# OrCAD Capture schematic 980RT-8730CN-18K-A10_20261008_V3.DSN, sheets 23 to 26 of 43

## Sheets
23 P0071_S7_DUT1: size Custom
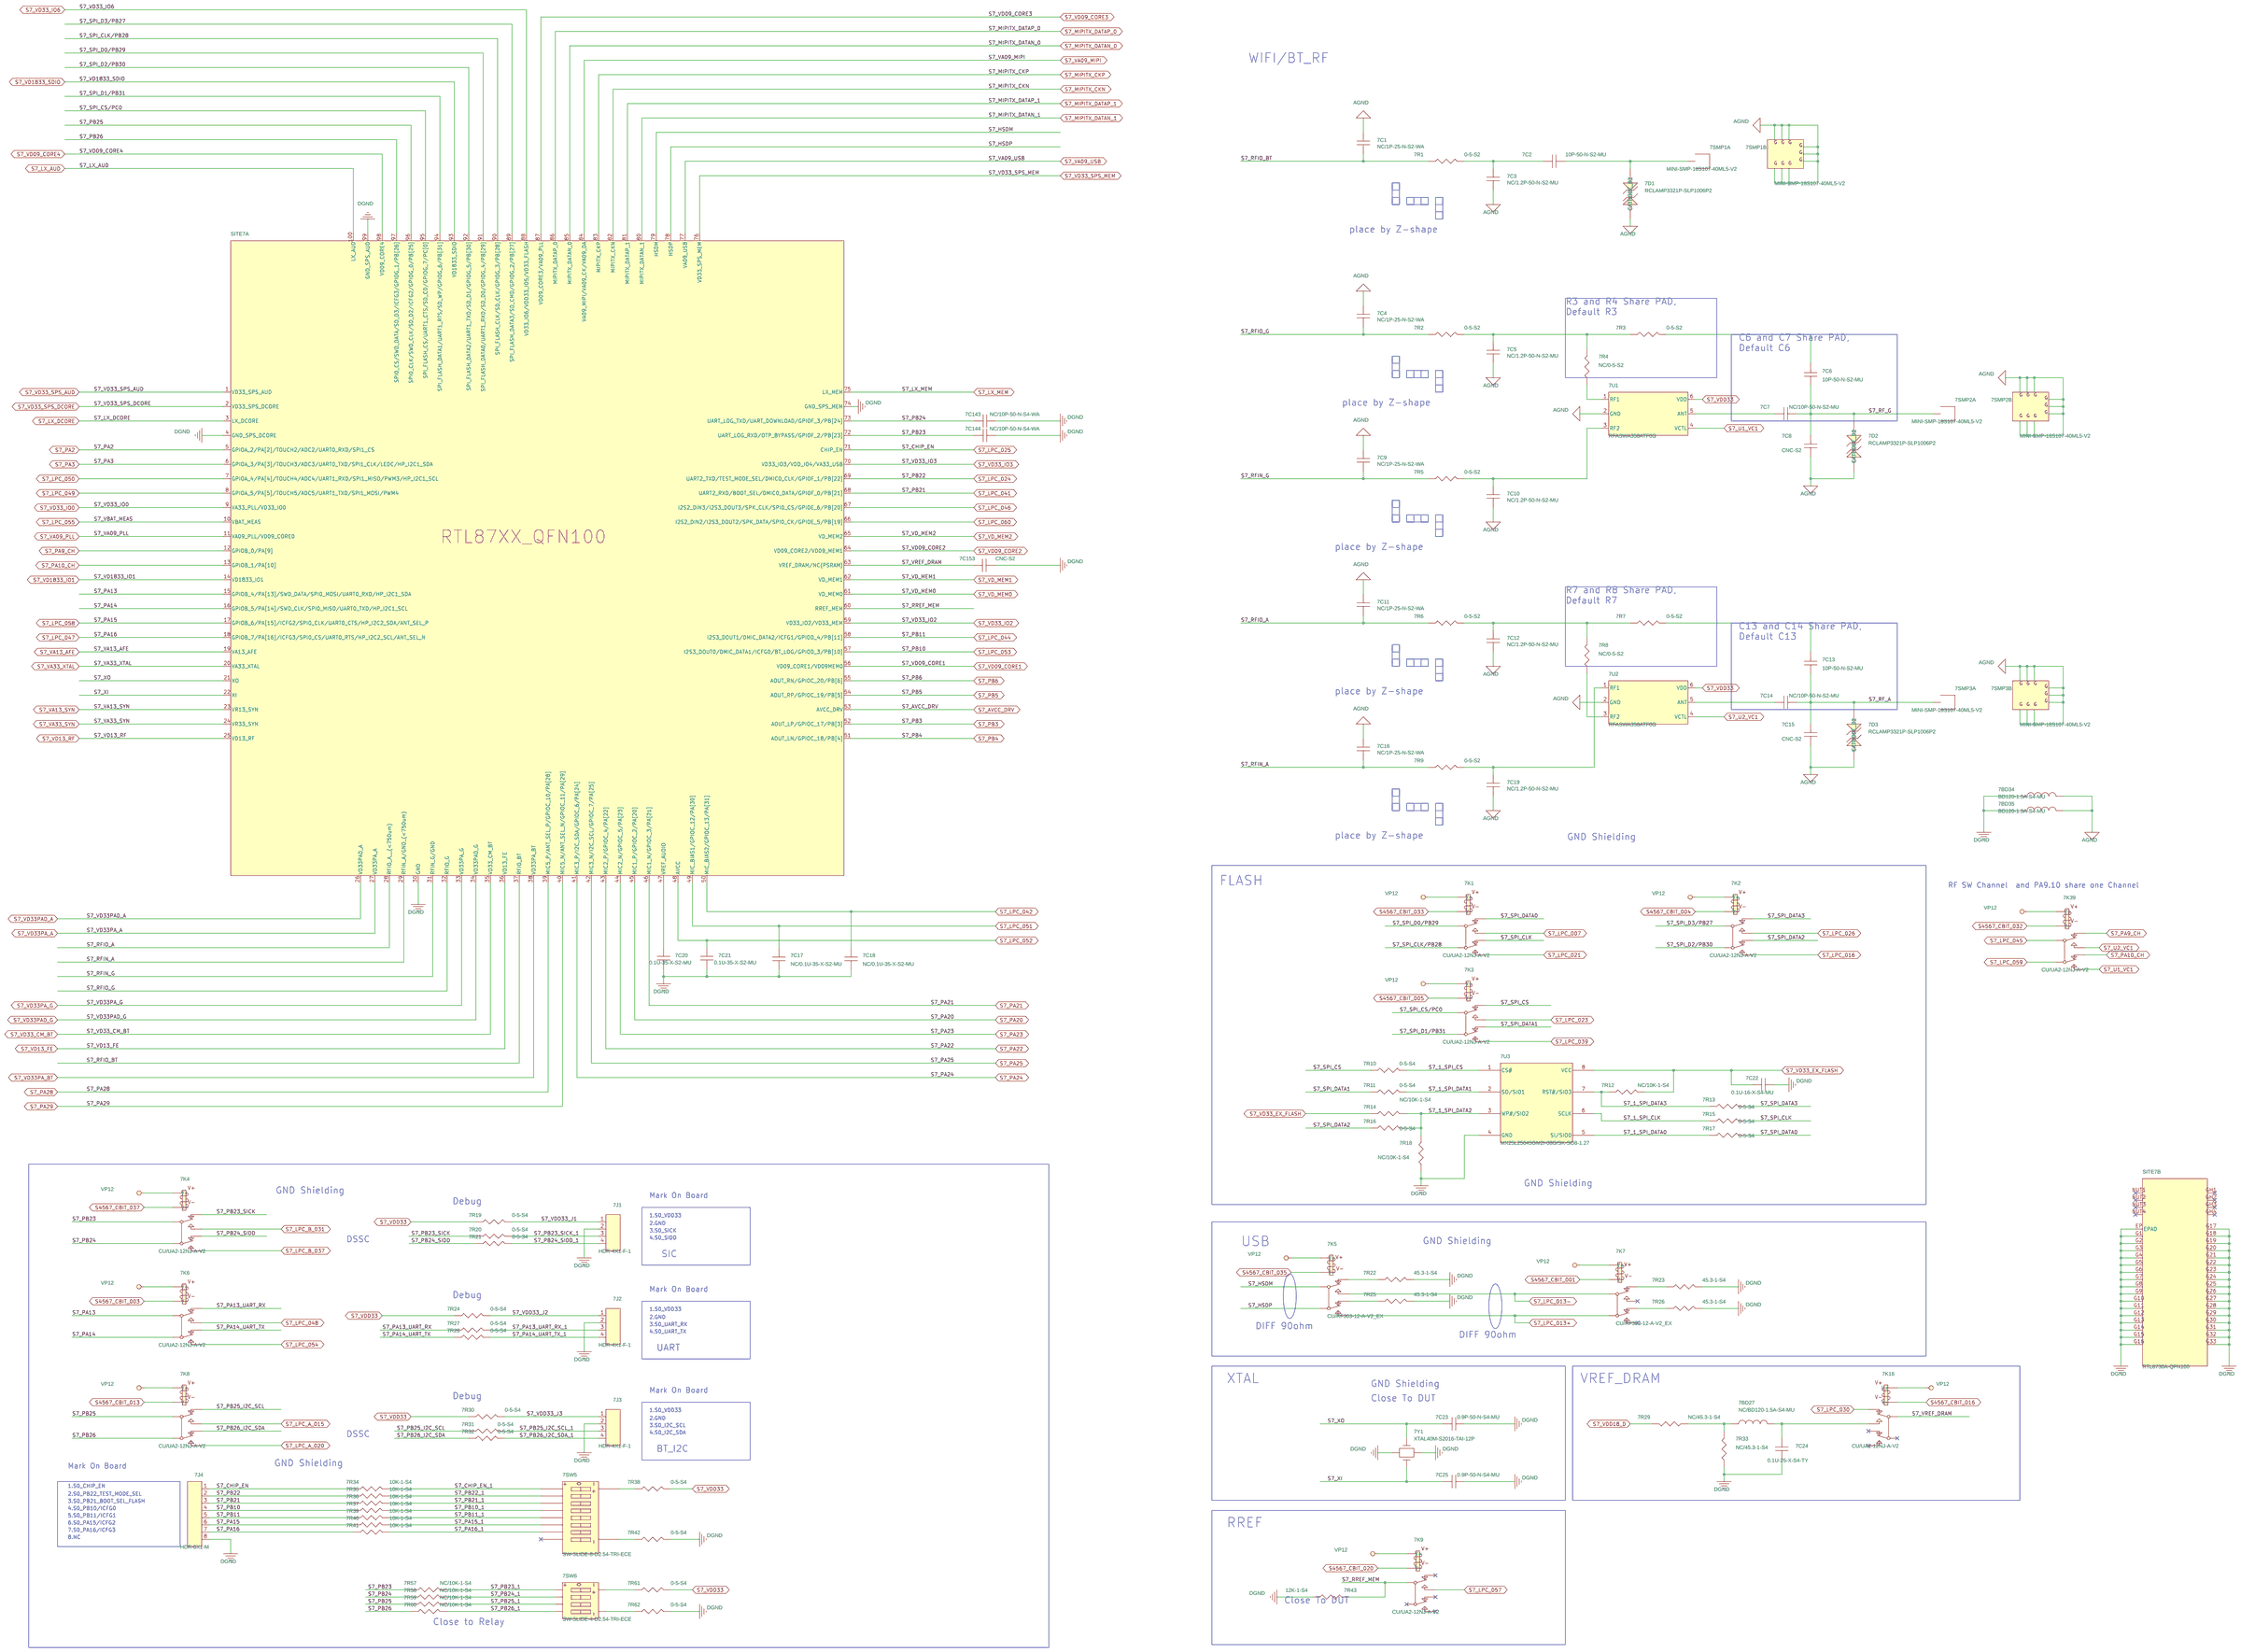
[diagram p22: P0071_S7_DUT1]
24 P0072_S7_Function-test: size A3
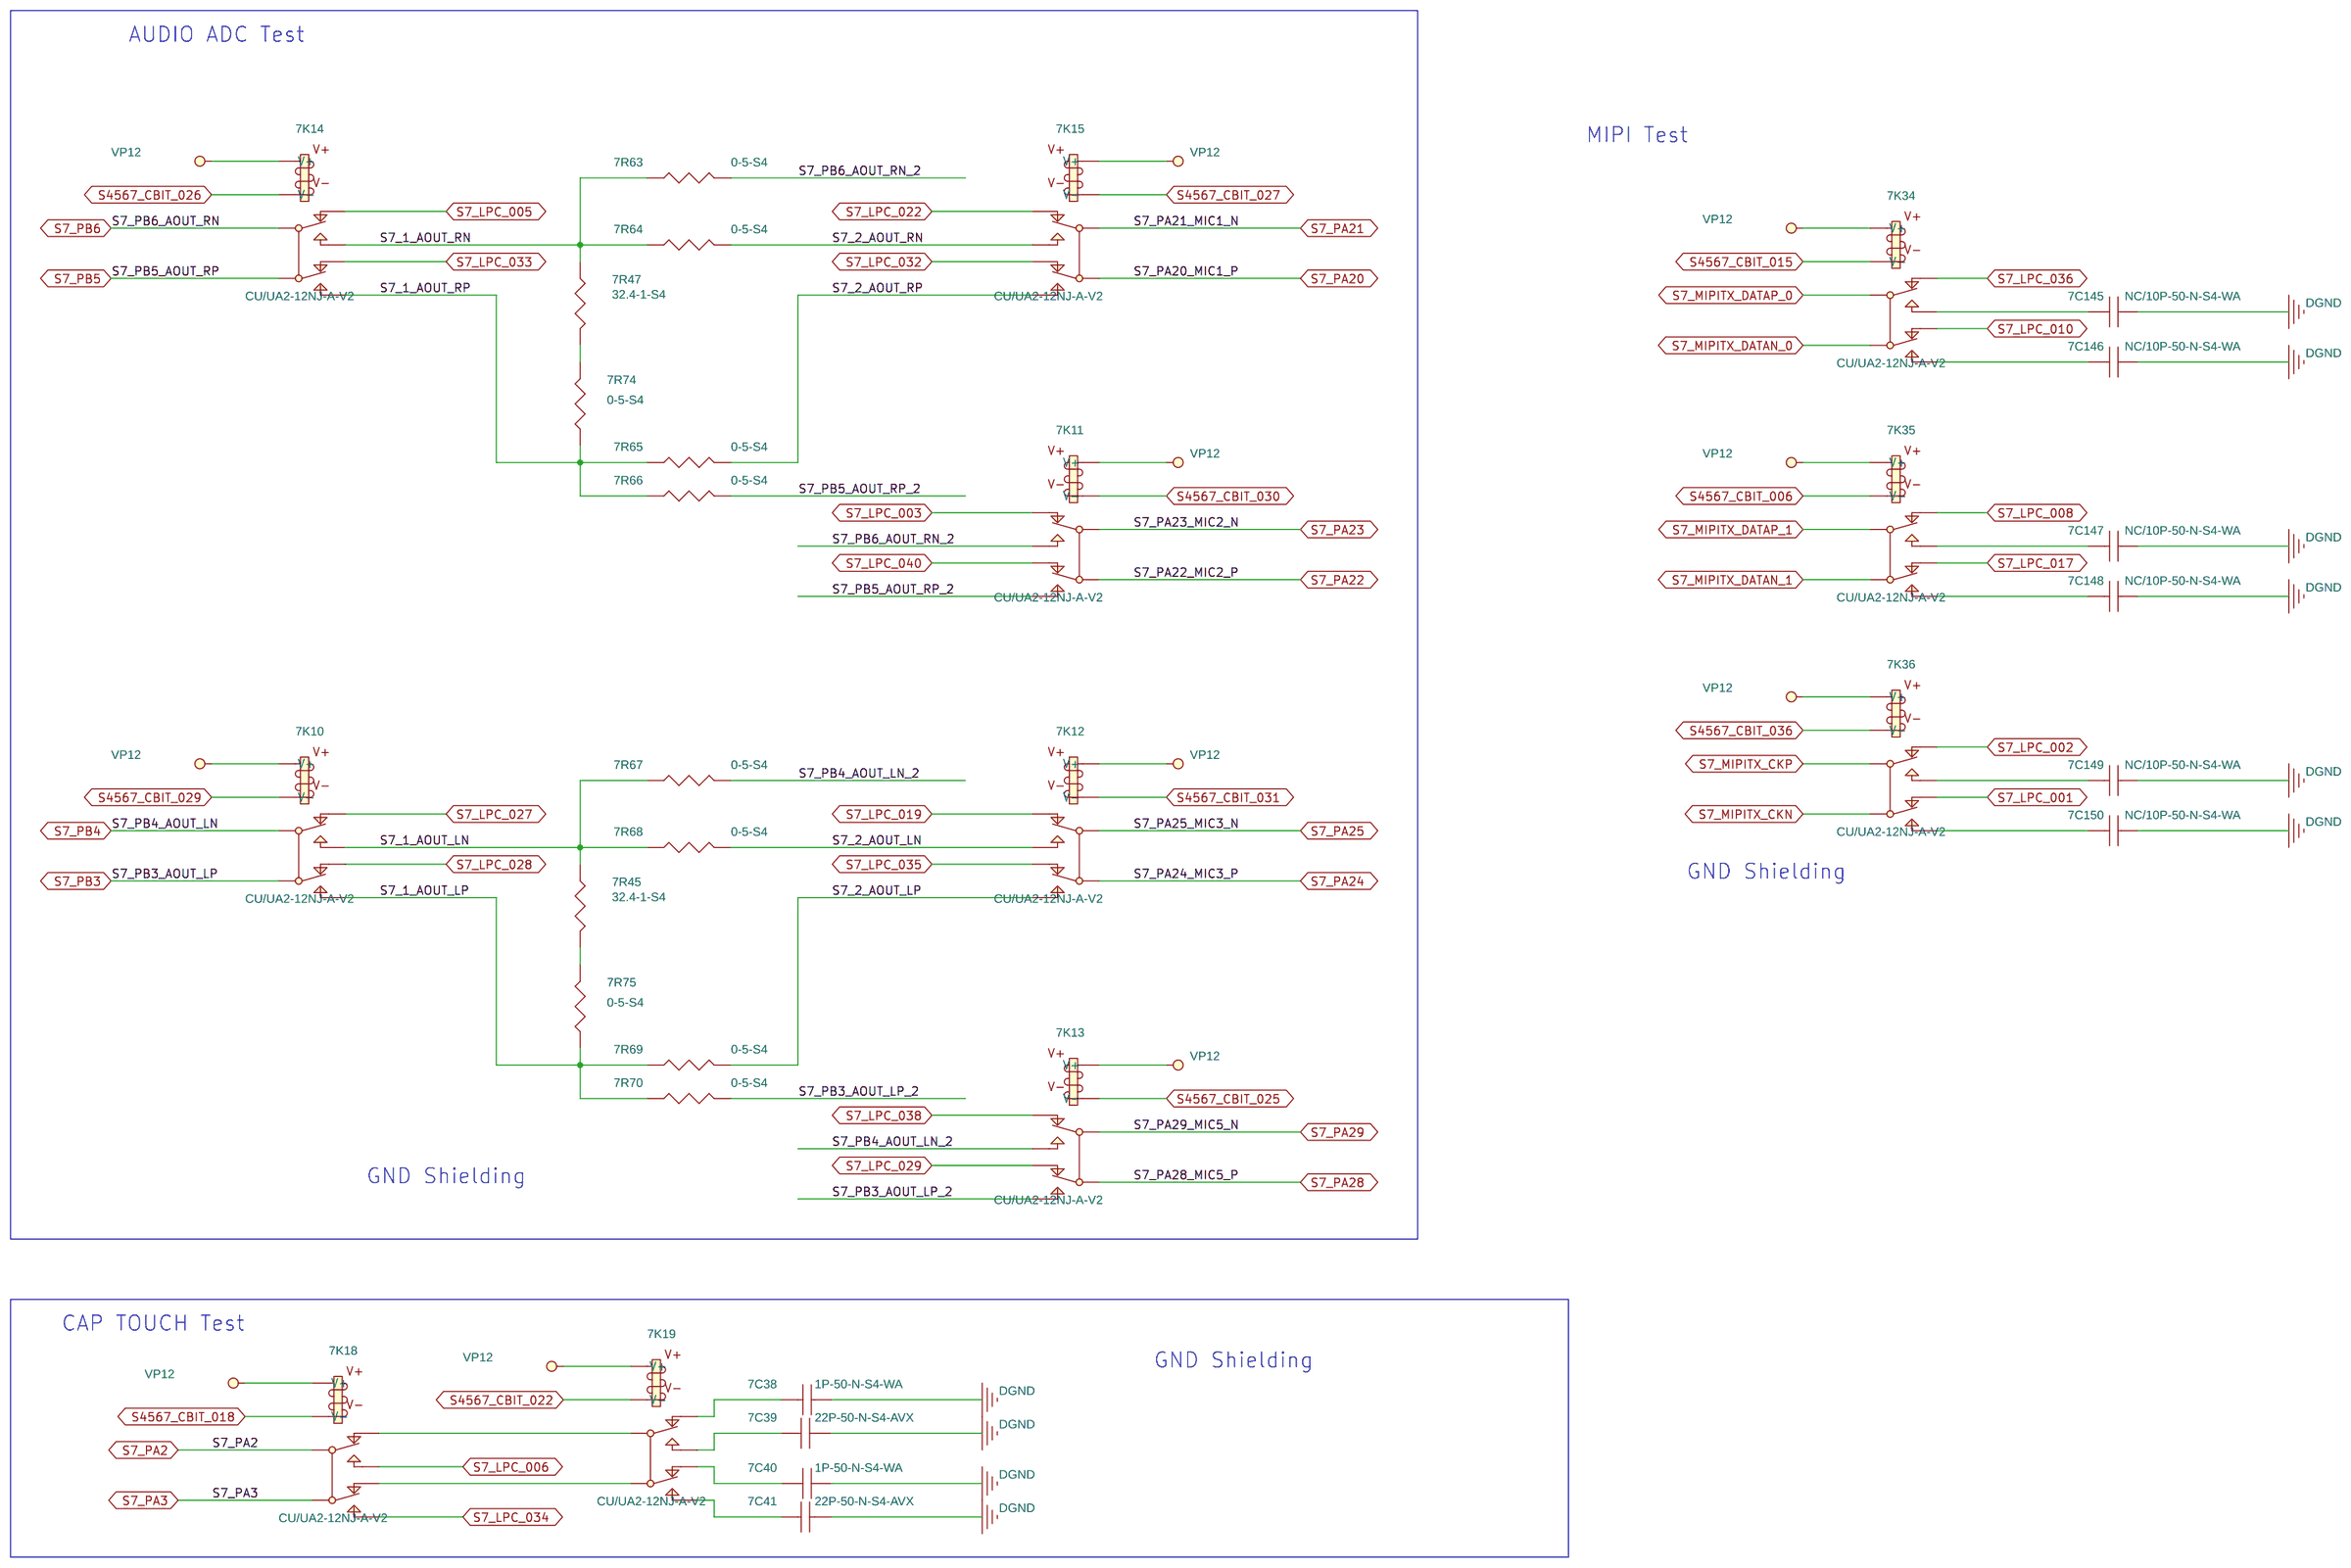
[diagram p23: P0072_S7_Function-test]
25 P0073_S7_Power: size A1
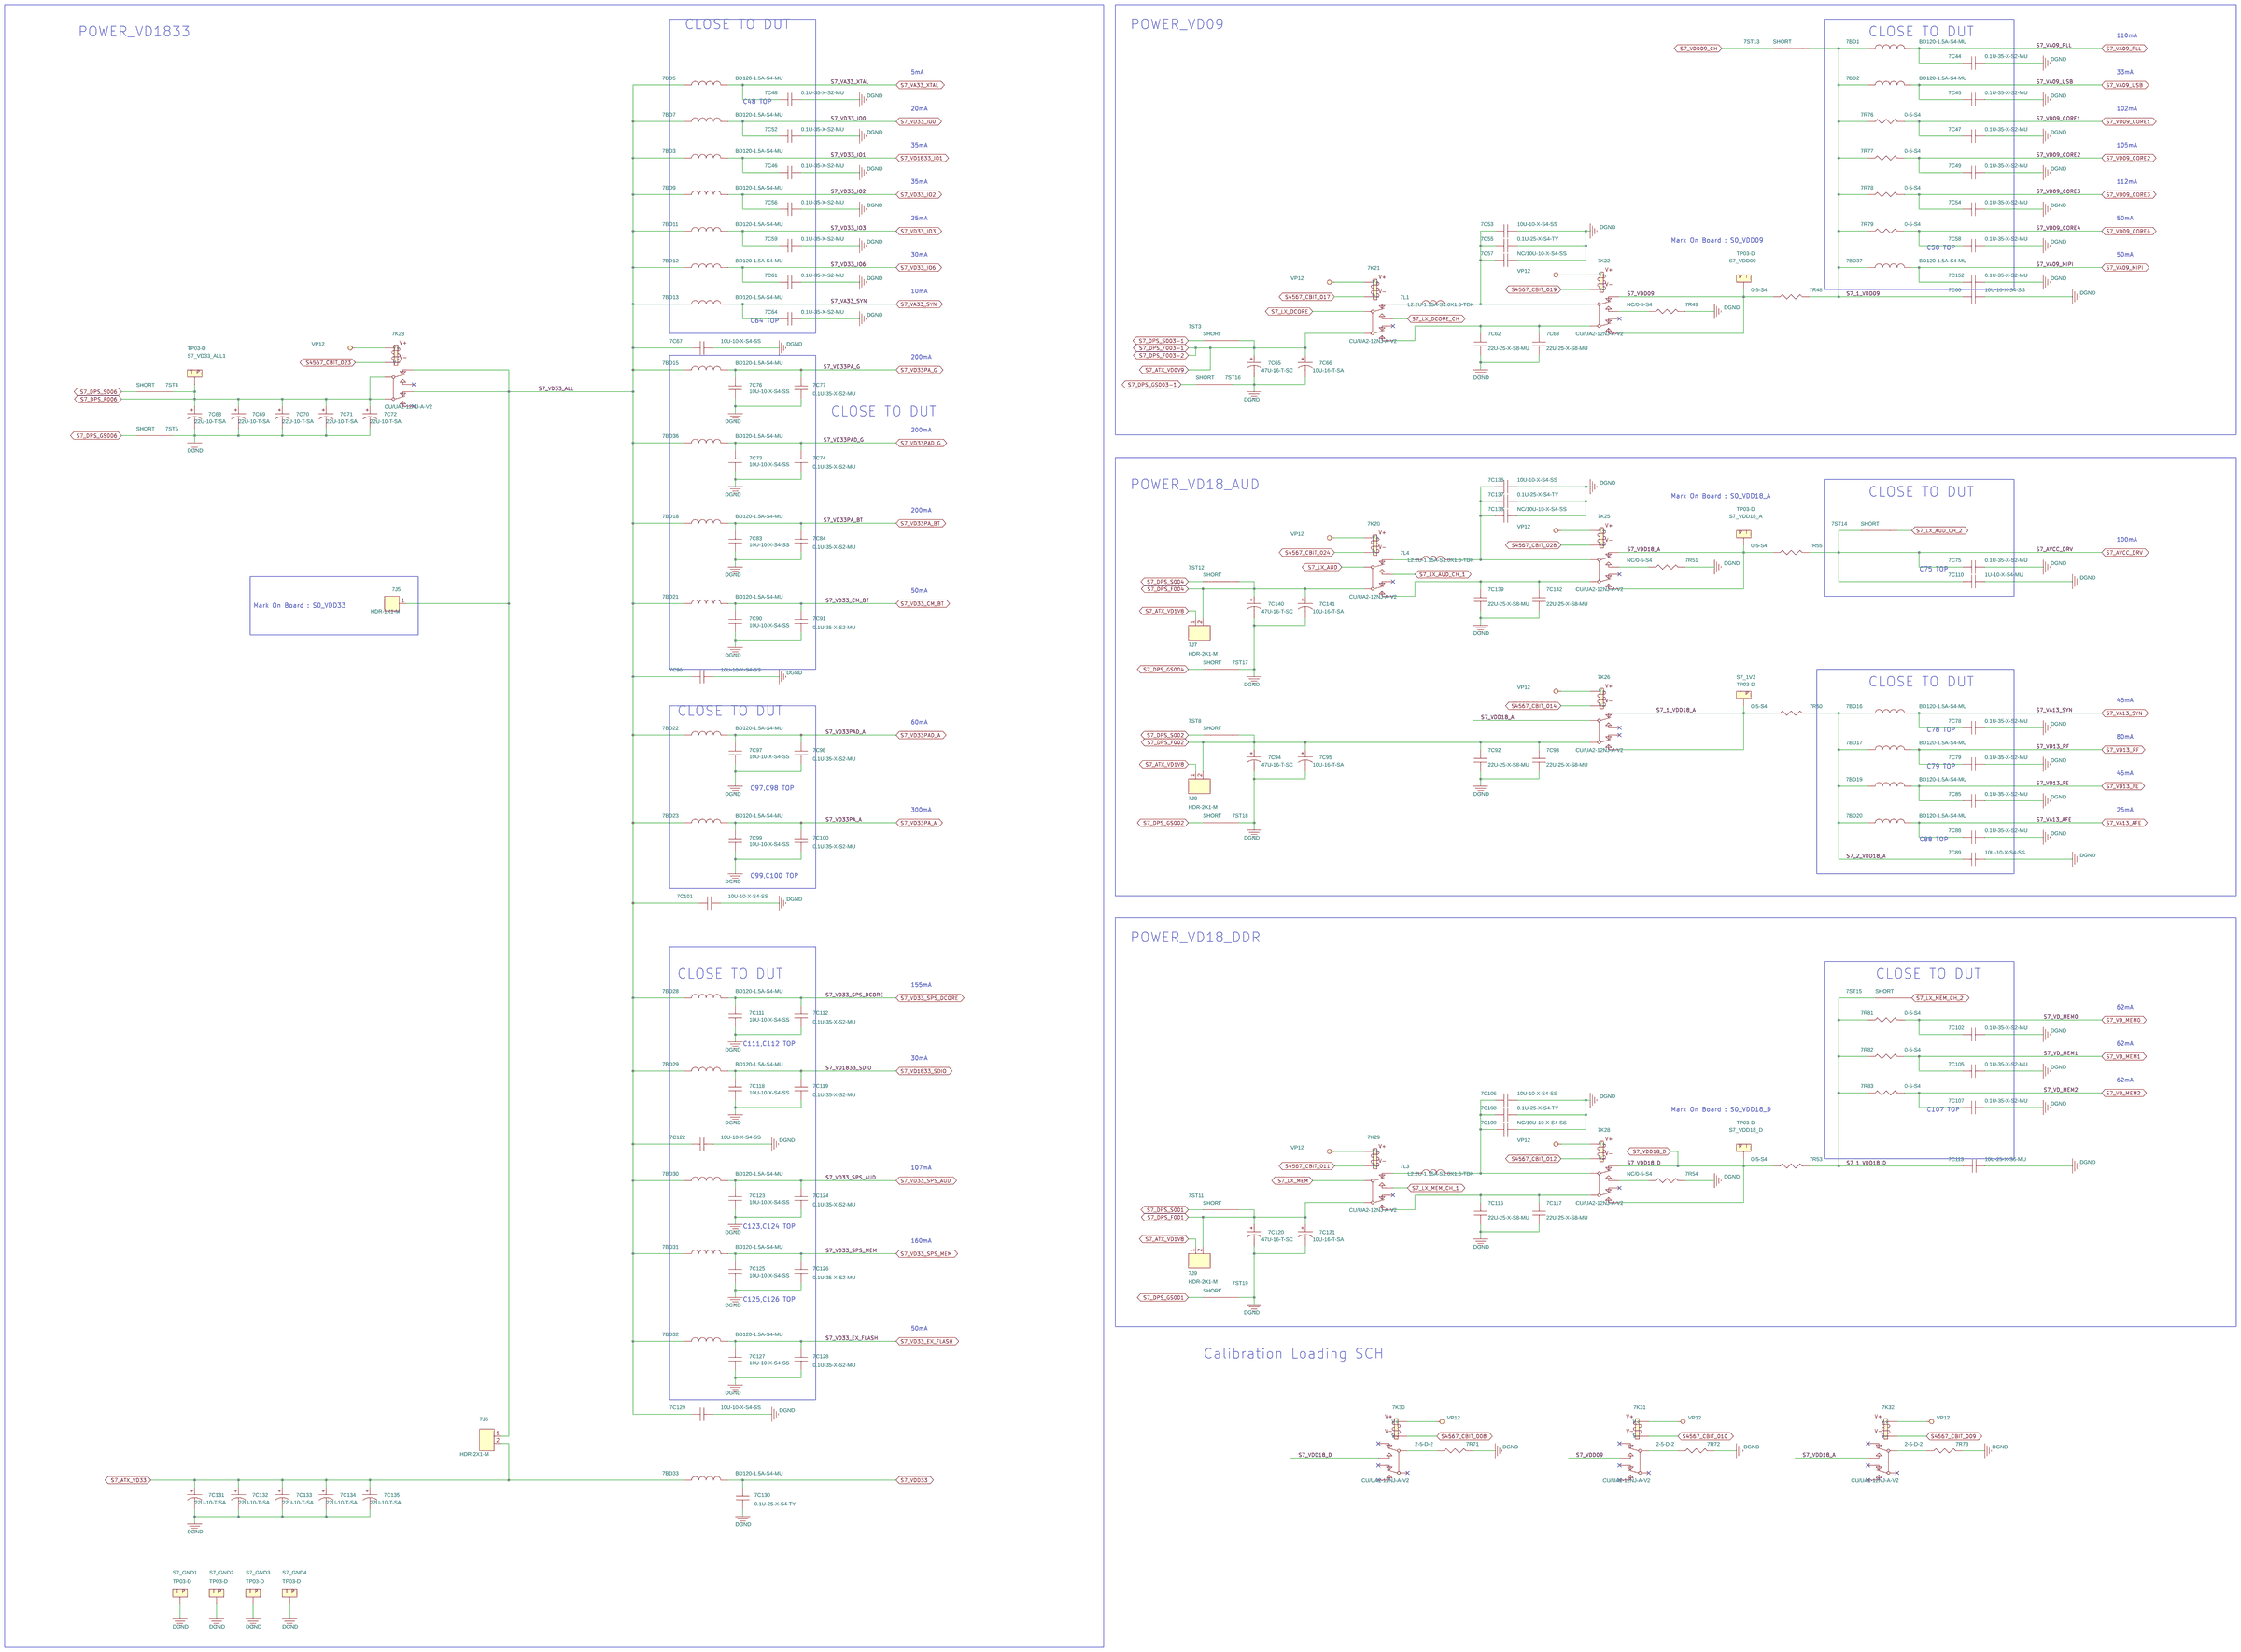
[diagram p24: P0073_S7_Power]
26 S0096_For_Temp: size A4
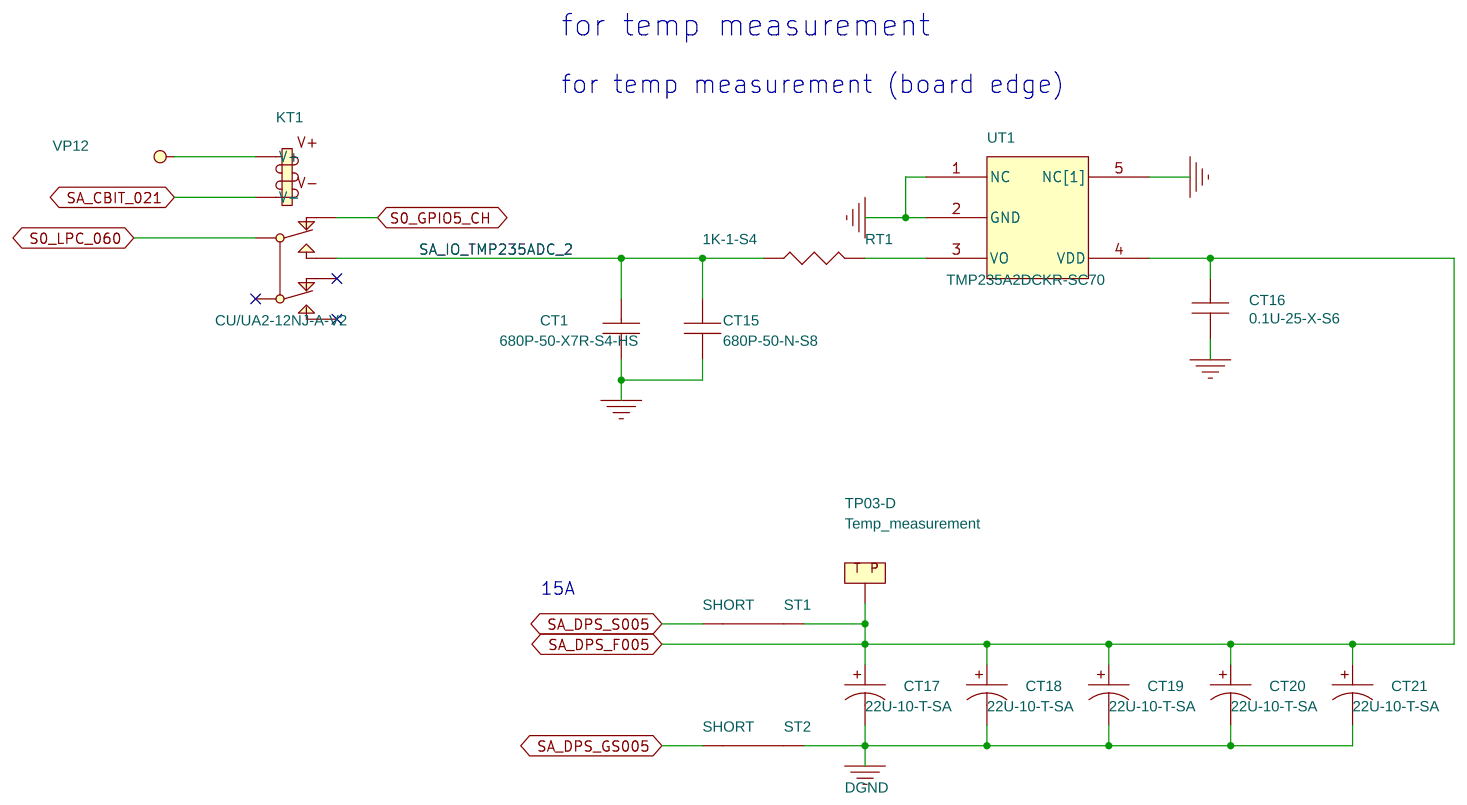
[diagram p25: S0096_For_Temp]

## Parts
sheet P0071_S7_DUT1
7BD27  NC/BD120-1.5A-S4-MU  [FB0402]
7BD34  BD120-1.5A-S4-MU  [FB0402]
7BD35  BD120-1.5A-S4-MU  [FB0402]
7C1  NC/1P-25-N-S2-WA  [C0201]
7C2  10P-50-N-S2-MU  [C0201]
7C3  NC/1.2P-50-N-S2-MU  [C0201]
7C4  NC/1P-25-N-S2-WA  [C0201]
7C5  NC/1.2P-50-N-S2-MU  [C0201]
7C6  10P-50-N-S2-MU  [C0201]
7C7  NC/10P-50-N-S2-MU  [C0201]
7C8  CNC-S2  [C0201]
7C9  NC/1P-25-N-S2-WA  [C0201]
7C10  NC/1.2P-50-N-S2-MU  [C0201]
7C11  NC/1P-25-N-S2-WA  [C0201]
7C12  NC/1.2P-50-N-S2-MU  [C0201]
7C13  10P-50-N-S2-MU  [C0201]
7C14  NC/10P-50-N-S2-MU  [C0201]
7C15  CNC-S2  [C0201]
7C16  NC/1P-25-N-S2-WA  [C0201]
7C17  NC/0.1U-35-X-S2-MU  [C0201]
7C18  NC/0.1U-35-X-S2-MU  [C0201]
7C19  NC/1.2P-50-N-S2-MU  [C0201]
7C20  0.1U-35-X-S2-MU  [C0201]
7C21  0.1U-35-X-S2-MU  [C0201]
7C22  0.1U-16-X-S4-MU  [C0402]
7C23  0.9P-50-N-S4-MU  [C0402]
7C24  0.1U-25-X-S4-TY  [C0402]
7C25  0.9P-50-N-S4-MU  [C0402]
7C143  NC/10P-50-N-S4-WA  [C0402]
7C144  NC/10P-50-N-S4-WA  [C0402]
7C153  CNC-S2  [C0201]
7D1  RCLAMP3321P-SLP1006P2  [DIODE_1X0P6MM]
7D2  RCLAMP3321P-SLP1006P2  [DIODE_1X0P6MM]
7D3  RCLAMP3321P-SLP1006P2  [DIODE_1X0P6MM]
7J1  HDR-4X1-F-1  [CONN_4X1_2P54MM_FL10P5MM]
7J2  HDR-4X1-F-1  [CONN_4X1_2P54MM_FL10P5MM]
7J3  HDR-4X1-F-1  [CONN_4X1_2P54MM_FL10P5MM]
7J4  HDR-8X1-M  [JP_8P_100]
7K1  CU/UA2-12NJ-A-V2  [RL_NECUA2_12V_V2]
7K2  CU/UA2-12NJ-A-V2  [RL_NECUA2_12V_V2]
7K3  CU/UA2-12NJ-A-V2  [RL_NECUA2_12V_V2]
7K4  CU/UA2-12NJ-A-V2  [RL_NECUA2_12V_V2]
7K5  CU/RF303-12-A-V2_EX  [RL_RF303_12V_V2]
7K6  CU/UA2-12NJ-A-V2  [RL_NECUA2_12V_V2]
7K7  CU/RF303-12-A-V2_EX  [RL_RF303_12V_V2]
7K8  CU/UA2-12NJ-A-V2  [RL_NECUA2_12V_V2]
7K9  CU/UA2-12NJ-A-V2  [RL_NECUA2_12V_V2]
7K16  CU/UA2-12NJ-A-V2  [RL_NECUA2_12V_V2]
7K39  CU/UA2-12NJ-A-V2  [RL_NECUA2_12V_V2]
7R1  0-5-S2  [R0201]
7R2  0-5-S2  [R0201]
7R3  0-5-S2  [R0201]
7R4  NC/0-5-S2  [R0201]
7R5  0-5-S2  [R0201]
7R6  0-5-S2  [R0201]
7R7  0-5-S2  [R0201]
7R8  NC/0-5-S2  [R0201]
7R9  0-5-S2  [R0201]
7R10  0-5-S4  [R0402]
7R11  0-5-S4  [R0402]
7R12  NC/10K-1-S4  [R0402]
7R13  0-5-S4  [R0402]
7R14  NC/10K-1-S4  [R0402]
7R15  0-5-S4  [R0402]
7R16  0-5-S4  [R0402]
7R17  0-5-S4  [R0402]
7R18  NC/10K-1-S4  [R0402]
7R19  0-5-S4  [R0402]
7R20  0-5-S4  [R0402]
7R21  0-5-S4  [R0402]
7R22  45.3-1-S4  [R0402]
7R23  45.3-1-S4  [R0402]
7R24  0-5-S4  [R0402]
7R25  45.3-1-S4  [R0402]
7R26  45.3-1-S4  [R0402]
7R27  0-5-S4  [R0402]
7R28  0-5-S4  [R0402]
7R29  NC/45.3-1-S4  [R0402]
7R30  0-5-S4  [R0402]
7R31  0-5-S4  [R0402]
7R32  0-5-S4  [R0402]
7R33  NC/45.3-1-S4  [R0402]
7R34  10K-1-S4  [R0402]
7R35  10K-1-S4  [R0402]
7R36  10K-1-S4  [R0402]
7R37  10K-1-S4  [R0402]
7R38  0-5-S4  [R0402]
7R39  10K-1-S4  [R0402]
7R40  10K-1-S4  [R0402]
7R41  10K-1-S4  [R0402]
7R42  0-5-S4  [R0402]
7R43  12K-1-S4  [R0402]
7R57  NC/10K-1-S4  [R0402]
7R58  NC/10K-1-S4  [R0402]
7R59  NC/10K-1-S4  [R0402]
7R60  NC/10K-1-S4  [R0402]
7R61  0-5-S4  [R0402]
7R62  0-5-S4  [R0402]
7SMP1  MINI-SMP-18S107-40ML5-V2  [CONN_SMP_18S107]  (sections A,B)
7SMP2  MINI-SMP-18S107-40ML5-V2  [CONN_SMP_18S107]  (sections A,B)
7SMP3  MINI-SMP-18S107-40ML5-V2  [CONN_SMP_18S107]  (sections A,B)
7SW5  SW-SLIDE-8-D2.54-TRI-ECE  [SW_DIPX8P_2P54_MM_V2]
7SW6  SW-SLIDE-4-D2.54-TRI-ECE  [SW_DIPX4P_2P54MM_ETD]
7U1  RFASWA358ATF0G  [RF_SW_GW2159_6P]
7U2  RFASWA358ATF0G  [RF_SW_GW2159_6P]
7U3  MX25L25645GM2I-08G/SK-SO8-1.27  [SK_SO8_1P27MM_LOTES]
7Y1  XTAL40M-S2016-TAI-12P  [XTAL_2X1P6MM_4P_0P8MM]
SITE7  RTL8730A-QFN100  [SK_QFN100P_0P35MM_MJC_L8730A]  (sections A,B)
sheet P0072_S7_Function-test
7C38  1P-50-N-S4-WA  [C0402]
7C39  22P-50-N-S4-AVX  [C0402]
7C40  1P-50-N-S4-WA  [C0402]
7C41  22P-50-N-S4-AVX  [C0402]
7C145  NC/10P-50-N-S4-WA  [C0402]
7C146  NC/10P-50-N-S4-WA  [C0402]
7C147  NC/10P-50-N-S4-WA  [C0402]
7C148  NC/10P-50-N-S4-WA  [C0402]
7C149  NC/10P-50-N-S4-WA  [C0402]
7C150  NC/10P-50-N-S4-WA  [C0402]
7K10  CU/UA2-12NJ-A-V2  [RL_NECUA2_12V_V2]
7K11  CU/UA2-12NJ-A-V2  [RL_NECUA2_12V_V2]
7K12  CU/UA2-12NJ-A-V2  [RL_NECUA2_12V_V2]
7K13  CU/UA2-12NJ-A-V2  [RL_NECUA2_12V_V2]
7K14  CU/UA2-12NJ-A-V2  [RL_NECUA2_12V_V2]
7K15  CU/UA2-12NJ-A-V2  [RL_NECUA2_12V_V2]
7K18  CU/UA2-12NJ-A-V2  [RL_NECUA2_12V_V2]
7K19  CU/UA2-12NJ-A-V2  [RL_NECUA2_12V_V2]
7K34  CU/UA2-12NJ-A-V2  [RL_NECUA2_12V_V2]
7K35  CU/UA2-12NJ-A-V2  [RL_NECUA2_12V_V2]
7K36  CU/UA2-12NJ-A-V2  [RL_NECUA2_12V_V2]
7R45  32.4-1-S4  [R0402]
7R47  32.4-1-S4  [R0402]
7R63  0-5-S4  [R0402]
7R64  0-5-S4  [R0402]
7R65  0-5-S4  [R0402]
7R66  0-5-S4  [R0402]
7R67  0-5-S4  [R0402]
7R68  0-5-S4  [R0402]
7R69  0-5-S4  [R0402]
7R70  0-5-S4  [R0402]
7R74  0-5-S4  [R0402]
7R75  0-5-S4  [R0402]
sheet P0073_S7_Power
7BD1  BD120-1.5A-S4-MU  [FB0402]
7BD2  BD120-1.5A-S4-MU  [FB0402]
7BD3  BD120-1.5A-S4-MU  [FB0402]
7BD5  BD120-1.5A-S4-MU  [FB0402]
7BD7  BD120-1.5A-S4-MU  [FB0402]
7BD9  BD120-1.5A-S4-MU  [FB0402]
7BD11  BD120-1.5A-S4-MU  [FB0402]
7BD12  BD120-1.5A-S4-MU  [FB0402]
7BD13  BD120-1.5A-S4-MU  [FB0402]
7BD15  BD120-1.5A-S4-MU  [FB0402]
7BD16  BD120-1.5A-S4-MU  [FB0402]
7BD17  BD120-1.5A-S4-MU  [FB0402]
7BD18  BD120-1.5A-S4-MU  [FB0402]
7BD19  BD120-1.5A-S4-MU  [FB0402]
7BD20  BD120-1.5A-S4-MU  [FB0402]
7BD21  BD120-1.5A-S4-MU  [FB0402]
7BD22  BD120-1.5A-S4-MU  [FB0402]
7BD23  BD120-1.5A-S4-MU  [FB0402]
7BD28  BD120-1.5A-S4-MU  [FB0402]
7BD29  BD120-1.5A-S4-MU  [FB0402]
7BD30  BD120-1.5A-S4-MU  [FB0402]
7BD31  BD120-1.5A-S4-MU  [FB0402]
7BD32  BD120-1.5A-S4-MU  [FB0402]
7BD33  BD120-1.5A-S4-MU  [FB0402]
7BD36  BD120-1.5A-S4-MU  [FB0402]
7BD37  BD120-1.5A-S4-MU  [FB0402]
7C44  0.1U-35-X-S2-MU  [C0201]
7C45  0.1U-35-X-S2-MU  [C0201]
7C46  0.1U-35-X-S2-MU  [C0201]
7C47  0.1U-35-X-S2-MU  [C0201]
7C48  0.1U-35-X-S2-MU  [C0201]
7C49  0.1U-35-X-S2-MU  [C0201]
7C52  0.1U-35-X-S2-MU  [C0201]
7C53  10U-10-X-S4-SS  [C0402]
7C54  0.1U-35-X-S2-MU  [C0201]
7C55  0.1U-25-X-S4-TY  [C0402]
7C56  0.1U-35-X-S2-MU  [C0201]
7C57  NC/10U-10-X-S4-SS  [C0402]
7C58  0.1U-35-X-S2-MU  [C0201]
7C59  0.1U-35-X-S2-MU  [C0201]
7C60  10U-10-X-S4-SS  [C0402]
7C61  0.1U-35-X-S2-MU  [C0201]
7C62  22U-25-X-S8-MU  [C0805]
7C63  22U-25-X-S8-MU  [C0805]
7C64  0.1U-35-X-S2-MU  [C0201]
7C65  47U-16-T-SC  [CODE_C]
7C66  10U-16-T-SA  [CODE_A]
7C67  10U-10-X-S4-SS  [C0402]
7C68  22U-10-T-SA  [CODE_A]
7C69  22U-10-T-SA  [CODE_A]
7C70  22U-10-T-SA  [CODE_A]
7C71  22U-10-T-SA  [CODE_A]
7C72  22U-10-T-SA  [CODE_A]
7C73  10U-10-X-S4-SS  [C0402]
7C74  0.1U-35-X-S2-MU  [C0201]
7C75  0.1U-35-X-S2-MU  [C0201]
7C76  10U-10-X-S4-SS  [C0402]
7C77  0.1U-35-X-S2-MU  [C0201]
7C78  0.1U-35-X-S2-MU  [C0201]
7C79  0.1U-35-X-S2-MU  [C0201]
7C83  10U-10-X-S4-SS  [C0402]
7C84  0.1U-35-X-S2-MU  [C0201]
7C85  0.1U-35-X-S2-MU  [C0201]
7C88  0.1U-35-X-S2-MU  [C0201]
7C89  10U-10-X-S4-SS  [C0402]
7C90  10U-10-X-S4-SS  [C0402]
7C91  0.1U-35-X-S2-MU  [C0201]
7C92  22U-25-X-S8-MU  [C0805]
7C93  22U-25-X-S8-MU  [C0805]
7C94  47U-16-T-SC  [CODE_C]
7C95  10U-16-T-SA  [CODE_A]
7C96  10U-10-X-S4-SS  [C0402]
7C97  10U-10-X-S4-SS  [C0402]
7C98  0.1U-35-X-S2-MU  [C0201]
7C99  10U-10-X-S4-SS  [C0402]
7C100  0.1U-35-X-S2-MU  [C0201]
7C101  10U-10-X-S4-SS  [C0402]
7C102  0.1U-35-X-S2-MU  [C0201]
7C105  0.1U-35-X-S2-MU  [C0201]
7C106  10U-10-X-S4-SS  [C0402]
7C107  0.1U-35-X-S2-MU  [C0201]
7C108  0.1U-25-X-S4-TY  [C0402]
7C109  NC/10U-10-X-S4-SS  [C0402]
7C110  1U-10-X-S4-MU  [C0402]
7C111  10U-10-X-S4-SS  [C0402]
7C112  0.1U-35-X-S2-MU  [C0201]
7C113  10U-25-X-S6-MU  [C0603]
7C116  22U-25-X-S8-MU  [C0805]
7C117  22U-25-X-S8-MU  [C0805]
7C118  10U-10-X-S4-SS  [C0402]
7C119  0.1U-35-X-S2-MU  [C0201]
7C120  47U-16-T-SC  [CODE_C]
7C121  10U-16-T-SA  [CODE_A]
7C122  10U-10-X-S4-SS  [C0402]
7C123  10U-10-X-S4-SS  [C0402]
7C124  0.1U-35-X-S2-MU  [C0201]
7C125  10U-10-X-S4-SS  [C0402]
7C126  0.1U-35-X-S2-MU  [C0201]
7C127  10U-10-X-S4-SS  [C0402]
7C128  0.1U-35-X-S2-MU  [C0201]
7C129  10U-10-X-S4-SS  [C0402]
7C130  0.1U-25-X-S4-TY  [C0402]
7C131  22U-10-T-SA  [CODE_A]
7C132  22U-10-T-SA  [CODE_A]
7C133  22U-10-T-SA  [CODE_A]
7C134  22U-10-T-SA  [CODE_A]
7C135  22U-10-T-SA  [CODE_A]
7C136  10U-10-X-S4-SS  [C0402]
7C137  0.1U-25-X-S4-TY  [C0402]
7C138  NC/10U-10-X-S4-SS  [C0402]
7C139  22U-25-X-S8-MU  [C0805]
7C140  47U-16-T-SC  [CODE_C]
7C141  10U-16-T-SA  [CODE_A]
7C142  22U-25-X-S8-MU  [C0805]
7C152  0.1U-35-X-S2-MU  [C0201]
7J5  HDR-1X1-M  [JP_1P_RD070_040]
7J6  HDR-2X1-M  [JP_2P_100]
7J7  HDR-2X1-M  [JP_2P_100]
7J8  HDR-2X1-M  [JP_2P_100]
7J9  HDR-2X1-M  [JP_2P_100]
7K20  CU/UA2-12NJ-A-V2  [RL_NECUA2_12V_V2]
7K21  CU/UA2-12NJ-A-V2  [RL_NECUA2_12V_V2]
7K22  CU/UA2-12NJ-A-V2  [RL_NECUA2_12V_V2]
7K23  CU/UA2-12NJ-A-V2  [RL_NECUA2_12V_V2]
7K25  CU/UA2-12NJ-A-V2  [RL_NECUA2_12V_V2]
7K26  CU/UA2-12NJ-A-V2  [RL_NECUA2_12V_V2]
7K28  CU/UA2-12NJ-A-V2  [RL_NECUA2_12V_V2]
7K29  CU/UA2-12NJ-A-V2  [RL_NECUA2_12V_V2]
7K30  CU/UA2-12NJ-A-V2  [RL_NECUA2_12V_V2]
7K31  CU/UA2-12NJ-A-V2  [RL_NECUA2_12V_V2]
7K32  CU/UA2-12NJ-A-V2  [RL_NECUA2_12V_V2]
7L1  L2.2U-1.15A-S2.0X1.6-TDK  [IND_VL252012E]
7L3  L2.2U-1.15A-S2.0X1.6-TDK  [IND_VL252012E]
7L4  L2.2U-1.15A-S2.0X1.6-TDK  [IND_VL252012E]
7R48  0-5-S4  [R0402]
7R49  NC/0-5-S4  [R0402]
7R50  0-5-S4  [R0402]
7R51  NC/0-5-S4  [R0402]
7R53  0-5-S4  [R0402]
7R54  NC/0-5-S4  [R0402]
7R55  0-5-S4  [R0402]
7R71  2-5-D-2  [RC02W_27MM]
7R72  2-5-D-2  [RC02W_27MM]
7R73  2-5-D-2  [RC02W_27MM]
7R76  0-5-S4  [R0402]
7R77  0-5-S4  [R0402]
7R78  0-5-S4  [R0402]
7R79  0-5-S4  [R0402]
7R81  0-5-S4  [R0402]
7R82  0-5-S4  [R0402]
7R83  0-5-S4  [R0402]
7ST3  SHORT  [DEFAULT_SHORT_SMALL]
7ST4  SHORT  [DEFAULT_SHORT_SMALL]
7ST5  SHORT  [DEFAULT_SHORT_SMALL]
7ST8  SHORT  [DEFAULT_SHORT_SMALL]
7ST11  SHORT  [DEFAULT_SHORT_SMALL]
7ST12  SHORT  [DEFAULT_SHORT_SMALL]
7ST13  SHORT  [DEFAULT_SHORT_SMALL]
7ST14  SHORT  [DEFAULT_SHORT_SMALL]
7ST15  SHORT  [DEFAULT_SHORT_SMALL]
7ST16  SHORT  [DEFAULT_SHORT_SMALL]
7ST17  SHORT  [DEFAULT_SHORT_SMALL]
7ST18  SHORT  [DEFAULT_SHORT_SMALL]
7ST19  SHORT  [DEFAULT_SHORT_SMALL]
S7_1V3  TP03-D  [TP_060_040]
S7_GND1  TP03-D  [TP_060_040]
S7_GND2  TP03-D  [TP_060_040]
S7_GND3  TP03-D  [TP_060_040]
S7_GND4  TP03-D  [TP_060_040]
S7_VD33_ALL1  TP03-D  [TP_060_040]
S7_VDD09  TP03-D  [TP_060_040]
S7_VDD18_A  TP03-D  [TP_060_040]
S7_VDD18_D  TP03-D  [TP_060_040]
sheet S0096_For_Temp
CT1  680P-50-X7R-S4-HS  [C0402]
CT15  680P-50-N-S8  [C0805]
CT16  0.1U-25-X-S6  [C0603]
CT17  22U-10-T-SA  [CODE_A]
CT18  22U-10-T-SA  [CODE_A]
CT19  22U-10-T-SA  [CODE_A]
CT20  22U-10-T-SA  [CODE_A]
CT21  22U-10-T-SA  [CODE_A]
KT1  CU/UA2-12NJ-A-V2  [RL_NECUA2_12V_V2]
RT1  1K-1-S4  [R0402]
ST1  SHORT  [DEFAULT_SHORT_SMALL]
ST2  SHORT  [DEFAULT_SHORT_SMALL]
Temp_measurement  TP03-D  [TP_060_040]
UT1  TMP235A2DCKR-SC70  [SC70_5P]

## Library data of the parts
7BD27 = BD120-1.5A-S4-MU: KAIROSNAME: BD27
7BD34 = BD120-1.5A-S4-MU: KAIROSNAME: BD34
7BD35 = BD120-1.5A-S4-MU: KAIROSNAME: BD35
7C1 7C4 7C9 7C11 7C16 = 1P-25-N-S2-WA
7C2 7C6 7C7 7C13 7C14 = 10P-50-N-S2-MU
7C3 7C5 7C10 7C12 7C19 = 1.2P-50-N-S2-MU
7C8 7C15 = CNC-S4
7C17 7C18 7C46 = 0.1U-35-X-S2-MU: KAIROSNAME: C46
7C20 7C21 7C98 = 0.1U-35-X-S2-MU: KAIROSNAME: C98
7C22 = 0.1U-16-X-S4: KAIROSNAME: C22
7C23 = 10P-50-N-S4-MU-1: KAIROSNAME: C23
7C24 = 0.1U-25-X-S4-TY: KAIROSNAME: C24
7C25 = 10P-50-N-S4-MU-1: KAIROSNAME: C25
7C143-7C150 = 10P-50-N-S4-WA
7C48 7C153 = 0.1U-35-X-S2-MU: KAIROSNAME: C48
7D1 = RCLAMP3321P-SLP1006P2: KAIROSNAME: D1
7D2 = RCLAMP3321P-SLP1006P2: KAIROSNAME: D2
7D3 = RCLAMP3321P-SLP1006P2: KAIROSNAME: D3
7J1-7J3 = HDR-4X1-F-1
7J4 = HDR-8X1-M: KAIROSNAME: J4
7K1 7K39 = CU_UA2-12NJ-A-V2: KAIROSNAME: K1
7K2 7K16 = CU_UA2-12NJ-A-V2: KAIROSNAME: K2
7K3 = CU_UA2-12NJ-A-V2: KAIROSNAME: K3
7K4 = CU_UA2-12NJ-A-V2: KAIROSNAME: K4
7K5 = CU_RF303-12-A-V2_EX: KAIROSNAME: K5
7K6 = CU_UA2-12NJ-A-V2: KAIROSNAME: K6
7K7 = CU_RF303-12-A-V2_EX: KAIROSNAME: K7
7K8 KT1 = CU_UA2-12NJ-A-V2: KAIROSNAME: K8
7K9 = CU_UA2-12NJ-A-V2: KAIROSNAME: K9
7R1-7R9 = 0-5-S2
7R10 = 0-5-S4: KAIROSNAME: R10
7R11 = 0-5-S4: KAIROSNAME: R11
7R12 = 10K-1-S4: KAIROSNAME: R12
7R13 = 0-5-S4: KAIROSNAME: R13
7R14 = 10K-1-S4: KAIROSNAME: R14
7R15 = 0-5-S4: KAIROSNAME: R15
7R16 = 0-5-S4: KAIROSNAME: R16
7R17 = 0-5-S4: KAIROSNAME: R17
7R18 = 10K-1-S4: KAIROSNAME: R18
7R19 = 0-5-S4: KAIROSNAME: R19
7R20 = 0-5-S4: KAIROSNAME: R20
7R21 = 0-5-S4: KAIROSNAME: R21
7R22 = 45.3-1-S4: KAIROSNAME: R22
7R23 = 45.3-1-S4: KAIROSNAME: R23
7R24 = 0-5-S4: KAIROSNAME: R24
7R25 = 45.3-1-S4: KAIROSNAME: R25
7R26 = 45.3-1-S4: KAIROSNAME: R26
7R27 = 0-5-S4: KAIROSNAME: R27
7R28 = 0-5-S4: KAIROSNAME: R28
7R29 = 45.3-1-S4: KAIROSNAME: R29
7R30 = 0-5-S4: KAIROSNAME: R30
7R31 = 0-5-S4: KAIROSNAME: R31
7R32 = 0-5-S4: KAIROSNAME: R32
7R33 = 45.3-1-S4: KAIROSNAME: R33
7R34 = 10K-1-S4: KAIROSNAME: R34
7R35 = 10K-1-S4: KAIROSNAME: R35
7R36 = 10K-1-S4: KAIROSNAME: R36
7R37 = 10K-1-S4: KAIROSNAME: R37
7R38 = 0-5-S4: KAIROSNAME: R38
7R39 = 10K-1-S4: KAIROSNAME: R39
7R40 = 10K-1-S4: KAIROSNAME: R40
7R41 = 10K-1-S4: KAIROSNAME: R41
7R42 = 0-5-S4: KAIROSNAME: R42
7R43 = 12K-1-S4: KAIROSNAME: R43
7R57 = 10K-1-S4: KAIROSNAME: R57
7R58 = 10K-1-S4: KAIROSNAME: R58
7R59 = 10K-1-S4: KAIROSNAME: R59
7R60 = 10K-1-S4: KAIROSNAME: R60
7R61 = 0-5-S4: KAIROSNAME: R61
7R62 = 0-5-S4: KAIROSNAME: R62
7SMP1 = MINI-SMP-18S107-40ML5-V2: KAIROSNAME: SMP1A
7SMP2 = MINI-SMP-18S107-40ML5-V2: KAIROSNAME: SMP2A
7SMP3 = MINI-SMP-18S107-40ML5-V2: KAIROSNAME: SMP3A
7SW5 = SW-SLIDE-8-D2.54-TRI-ECE
7SW6 = SW-SLIDE-4-D2.54-TRI-ECE
7U1 7U2 = RFASWA358ATF0G
7U3 = MX25R6435FM2IL0-SOP8: KAIROSNAME: U3
7Y1 = XTAL40M-S2016-TAI-12P: KAIROSNAME: Y1
SITE7 = RTL8730A-QFN100
7C38 = 10P-50-N-S4-MU-1: KAIROSNAME: C38
7C39 = 33P-50-N-S4-WA: KAIROSNAME: C39
7C40 = 10P-50-N-S4-MU-1: KAIROSNAME: C40
7C41 = 33P-50-N-S4-WA: KAIROSNAME: C41
7K10 = CU_UA2-12NJ-A-V2: KAIROSNAME: K10
7K11 = CU_UA2-12NJ-A-V2: KAIROSNAME: K11
7K12 = CU_UA2-12NJ-A-V2: KAIROSNAME: K12
7K13 = CU_UA2-12NJ-A-V2: KAIROSNAME: K13
7K14 = CU_UA2-12NJ-A-V2: KAIROSNAME: K14
7K15 7K34-7K36 = CU_UA2-12NJ-A-V2: KAIROSNAME: K15
7K18 = CU_UA2-12NJ-A-V2: KAIROSNAME: K18
7K19 = CU_UA2-12NJ-A-V2: KAIROSNAME: K19
7R45 = 32.4-1-S4: KAIROSNAME: R45
7R47 = 32.4-1-S4: KAIROSNAME: R47
7R63 = 0-5-S4: KAIROSNAME: R63
7R64 = 0-5-S4: KAIROSNAME: R64
7R65 7R74 7R75 = 0-5-S4: KAIROSNAME: R65
7R66 = 0-5-S4: KAIROSNAME: R66
7R67 = 0-5-S4: KAIROSNAME: R67
7R68 = 0-5-S4: KAIROSNAME: R68
7R69 = 0-5-S4: KAIROSNAME: R69
7R70 = 0-5-S4: KAIROSNAME: R70
7BD1 = BD120-1.5A-S4-MU: KAIROSNAME: BD1
7BD2 = BD120-1.5A-S4-MU: KAIROSNAME: BD2
7BD3 = BD120-1.5A-S4-MU: KAIROSNAME: BD3
7BD5 = BD120-1.5A-S4-MU: KAIROSNAME: BD5
7BD7 = BD120-1.5A-S4-MU: KAIROSNAME: BD7
7BD9 = BD120-1.5A-S4-MU: KAIROSNAME: BD9
7BD11 = BD120-1.5A-S4-MU: KAIROSNAME: BD11
7BD12 = BD120-1.5A-S4-MU: KAIROSNAME: BD12
7BD13 = BD120-1.5A-S4-MU: KAIROSNAME: BD13
7BD15 7BD36 = BD120-1.5A-S4-MU: KAIROSNAME: BD15
7BD16 = BD120-1.5A-S4-MU: KAIROSNAME: BD16
7BD17 = BD120-1.5A-S4-MU: KAIROSNAME: BD17
7BD18 = BD120-1.5A-S4-MU: KAIROSNAME: BD18
7BD19 = BD120-1.5A-S4-MU: KAIROSNAME: BD19
7BD20 = BD120-1.5A-S4-MU: KAIROSNAME: BD20
7BD21 = BD120-1.5A-S4-MU: KAIROSNAME: BD21
7BD22 = BD120-1.5A-S4-MU: KAIROSNAME: BD22
7BD23 = BD120-1.5A-S4-MU: KAIROSNAME: BD23
7BD28 = BD120-1.5A-S4-MU: KAIROSNAME: BD28
7BD29 = BD120-1.5A-S4-MU: KAIROSNAME: BD29
7BD30 = BD120-1.5A-S4-MU: KAIROSNAME: BD30
7BD31 = BD120-1.5A-S4-MU: KAIROSNAME: BD31
7BD32 = BD120-1.5A-S4-MU: KAIROSNAME: BD32
7BD33 = BD120-1.5A-S4-MU: KAIROSNAME: BD33
7BD37 = BD120-1.5A-S4-MU: KAIROSNAME: BD10
7C44 = 0.1U-35-X-S2-MU: KAIROSNAME: C44
7C45 = 0.1U-35-X-S2-MU: KAIROSNAME: C45
7C47 = 0.1U-35-X-S2-MU: KAIROSNAME: C47
7C49 = 0.1U-35-X-S2-MU: KAIROSNAME: C49
7C52 = 0.1U-35-X-S2-MU: KAIROSNAME: C52
7C53 = 10U-10-X-S4-SS: KAIROSNAME: C53
7C54 = 0.1U-35-X-S2-MU: KAIROSNAME: C54
7C55 = 0.1U-25-X-S4-TY: KAIROSNAME: C55
7C56 = 0.1U-35-X-S2-MU: KAIROSNAME: C56
7C57 = 10U-10-X-S4-SS: KAIROSNAME: C57
7C58 7C152 = 0.1U-35-X-S2-MU: KAIROSNAME: C58
7C59 = 0.1U-35-X-S2-MU: KAIROSNAME: C59
7C60 = 10U-10-X-S4-SS: KAIROSNAME: C60
7C61 = 0.1U-35-X-S2-MU: KAIROSNAME: C61
7C62 = 22U-25-X-S8-MU: KAIROSNAME: C62
7C63 = 22U-25-X-S8-MU: KAIROSNAME: C63
7C64 = 0.1U-35-X-S2-MU: KAIROSNAME: C64
7C65 = 47U-16-T-SC: KAIROSNAME: C65
7C66 = 10U-16-T-SA: KAIROSNAME: C66
7C67 = 10U-10-X-S4-SS: KAIROSNAME: C67
7C68 CT17 = 22U-10-T-SA: KAIROSNAME: C68
7C69 CT18 = 22U-10-T-SA: KAIROSNAME: C69
7C70 CT19 = 22U-10-T-SA: KAIROSNAME: C70
7C71 CT20 = 22U-10-T-SA: KAIROSNAME: C71
7C72 CT21 = 22U-10-T-SA: KAIROSNAME: C72
7C73 7C76 = 10U-10-X-S4-SS: KAIROSNAME: C76
7C74 7C77 = 0.1U-35-X-S2-MU: KAIROSNAME: C77
7C75 = 0.1U-35-X-S2-MU: KAIROSNAME: C75
7C78 = 0.1U-35-X-S2-MU: KAIROSNAME: C78
7C79 = 0.1U-35-X-S2-MU: KAIROSNAME: C79
7C83 = 10U-10-X-S4-SS: KAIROSNAME: C83
7C84 = 0.1U-35-X-S2-MU: KAIROSNAME: C84
7C85 = 0.1U-35-X-S2-MU: KAIROSNAME: C85
7C88 = 0.1U-35-X-S2-MU: KAIROSNAME: C88
7C89 = 10U-10-X-S4-SS: KAIROSNAME: C89
7C90 = 10U-10-X-S4-SS: KAIROSNAME: C90
7C91 = 0.1U-35-X-S2-MU: KAIROSNAME: C91
7C92 = 22U-25-X-S8-MU: KAIROSNAME: C92
7C93 = 22U-25-X-S8-MU: KAIROSNAME: C93
7C94 = 47U-16-T-SC: KAIROSNAME: C94
7C95 = 10U-16-T-SA: KAIROSNAME: C95
7C96 = 10U-10-X-S4-SS: KAIROSNAME: C96
7C97 = 10U-10-X-S4-SS: KAIROSNAME: C97
7C99 = 10U-10-X-S4-SS: KAIROSNAME: C99
7C100 = 0.1U-35-X-S2-MU: KAIROSNAME: C100
7C101 = 10U-10-X-S4-SS: KAIROSNAME: C101
7C102 = 0.1U-35-X-S2-MU: KAIROSNAME: C102
7C105 = 0.1U-35-X-S2-MU: KAIROSNAME: C105
7C106 = 10U-10-X-S4-SS: KAIROSNAME: C106
7C107 = 0.1U-35-X-S2-MU: KAIROSNAME: C107
7C108 = 0.1U-25-X-S4-TY: KAIROSNAME: C108
7C109 = 10U-10-X-S4-SS: KAIROSNAME: C109
7C110 = 10U-10-X-S4-SS: KAIROSNAME: C110
7C111 = 10U-10-X-S4-SS: KAIROSNAME: C111
7C112 = 0.1U-35-X-S2-MU: KAIROSNAME: C112
7C113 = 10U-25-X-S6-MU: KAIROSNAME: C113
7C116 = 22U-25-X-S8-MU: KAIROSNAME: C116
7C117 = 22U-25-X-S8-MU: KAIROSNAME: C117
7C118 = 10U-10-X-S4-SS: KAIROSNAME: C118
7C119 = 0.1U-35-X-S2-MU: KAIROSNAME: C119
7C120 = 47U-16-T-SC: KAIROSNAME: C120
7C121 = 10U-16-T-SA: KAIROSNAME: C121
7C122 = 10U-10-X-S4-SS: KAIROSNAME: C122
7C123 = 10U-10-X-S4-SS: KAIROSNAME: C123
7C124 = 0.1U-35-X-S2-MU: KAIROSNAME: C124
7C125 = 10U-10-X-S4-SS: KAIROSNAME: C125
7C126 = 0.1U-35-X-S2-MU: KAIROSNAME: C126
7C127 = 10U-10-X-S4-SS: KAIROSNAME: C127
7C128 = 0.1U-35-X-S2-MU: KAIROSNAME: C128
7C129 = 10U-10-X-S4-SS: KAIROSNAME: C129
7C130 = 0.1U-25-X-S4-TY: KAIROSNAME: C130
7C131 = 22U-10-T-SA: KAIROSNAME: C131
7C132 = 22U-10-T-SA: KAIROSNAME: C132
7C133 = 22U-10-T-SA: KAIROSNAME: C133
7C134 = 22U-10-T-SA: KAIROSNAME: C134
7C135 = 22U-10-T-SA: KAIROSNAME: C135
7C136 = 10U-10-X-S4-SS: KAIROSNAME: C136
7C137 = 0.1U-25-X-S4-TY: KAIROSNAME: C137
7C138 = 10U-10-X-S4-SS: KAIROSNAME: C138
7C139 = 22U-25-X-S8-MU: KAIROSNAME: C139
7C140 = 47U-16-T-SC: KAIROSNAME: C140
7C141 = 10U-16-T-SA: KAIROSNAME: C141
7C142 = 22U-25-X-S8-MU: KAIROSNAME: C142
7J5 = HDR-1X1-M: KAIROSNAME: J5
7J6 = HDR-2X1-M: KAIROSNAME: J6
7J7 = HDR-2X1-M: KAIROSNAME: J7
7J8 = HDR-2X1-M: KAIROSNAME: J8
7J9 = HDR-2X1-M: KAIROSNAME: J9
7K20 = CU_UA2-12NJ-A-V2: KAIROSNAME: K20
7K21 = CU_UA2-12NJ-A-V2: KAIROSNAME: K21
7K22 = CU_UA2-12NJ-A-V2: KAIROSNAME: K22
7K23 = CU_UA2-12NJ-A-V2: KAIROSNAME: K23
7K25 = CU_UA2-12NJ-A-V2: KAIROSNAME: K25
7K26 = CU_UA2-12NJ-A-V2: KAIROSNAME: K26
7K28 7K30-7K32 = CU_UA2-12NJ-A-V2: KAIROSNAME: K28
7K29 = CU_UA2-12NJ-A-V2: KAIROSNAME: K29
7L1 = L2.2U-1.15A-S2.0X1.6-TDK: KAIROSNAME: L1
7L3 = L2.2U-1.15A-S2.0X1.6-TDK: KAIROSNAME: L3
7L4 = L2.2U-1.15A-S2.0X1.6-TDK: KAIROSNAME: L4
7R48 = 0-5-S4: KAIROSNAME: R48
7R49 = 0-5-S4: KAIROSNAME: R49
7R50 = 0-5-S4: KAIROSNAME: R50
7R51 = 0-5-S4: KAIROSNAME: R51
7R53 = 0-5-S4: KAIROSNAME: R53
7R54 = 0-5-S4: KAIROSNAME: R54
7R55 = 0-5-S4: KAIROSNAME: R55
7R71-7R73 = 2-5-D-2
7R76-7R79 7R81-7R83 = 0-5-S4
7ST3 7ST13-7ST15 = SHORT: KAIROSNAME: ST3
7ST4 ST1 = SHORT: KAIROSNAME: ST4
7ST5 7ST16-7ST19 ST2 = SHORT: KAIROSNAME: ST5
7ST8 = SHORT: KAIROSNAME: ST8
7ST11 = SHORT: KAIROSNAME: ST11
7ST12 = SHORT: KAIROSNAME: ST12
S7_1V3 = TP03-D: KAIROSNAME: S0_TP_VD3
S7_GND1 = TP03-D: KAIROSNAME: S0_GND1
S7_GND2 = TP03-D: KAIROSNAME: S0_GND2
S7_GND3 = TP03-D: KAIROSNAME: S0_GND3
S7_GND4 = TP03-D: KAIROSNAME: S0_GND4
S7_VD33_ALL1 Temp_measurement = TP03-D: KAIROSNAME: S0_VD33_ALL1
S7_VDD09 = TP03-D: KAIROSNAME: S0_VDD09
S7_VDD18_A = TP03-D: KAIROSNAME: S0_VDD18_A
S7_VDD18_D = TP03-D: KAIROSNAME: S0_VDD18_D
CT1 CT15 = 680P-50-X-S4
CT16 = 0.1U-25-X-S6
RT1 = 1K-1-S4
UT1 = TMP235_0

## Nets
AGND: 7BD34.2 7BD35.2 7C1.1 7C3.2 7C4.1 7C5.2 7C8.2 7C9.1 7C10.2 7C11.1 7C12.2 7C15.2 7C16.1 7C19.2 7D1.2(CATHODE_D2) 7D2.2(CATHODE_D2) 7D3.2(CATHODE_D2) 7SMP1.G1 7SMP1.G2 7SMP1.G3 7SMP1.G4 7SMP1.G5 7SMP1.G6 7SMP1.G7 7SMP1.G8 7SMP1.G9 7SMP2.G1 7SMP2.G2 7SMP2.G3 7SMP2.G4 7SMP2.G5 7SMP2.G6 7SMP2.G7 7SMP2.G8 7SMP2.G9 7SMP3.G1 7SMP3.G2 7SMP3.G3 7SMP3.G4 7SMP3.G5 7SMP3.G6 7SMP3.G7 7SMP3.G8 7SMP3.G9 7U1.2(GND) 7U2.2(GND) ; also on sheet 2 5 8 11 14 17 20
DGND: 7BD34.1 7BD35.1 7C17.1 7C18.1 7C20.2 7C21.2 7C22.2 7C23.1 7C24.2 7C25.1 7C38.1 7C39.2 7C40.1 7C41.2 7C44.2 7C45.2 7C46.2 7C47.2 7C48.2 7C49.2 7C52.2 7C53.2 7C54.2 7C55.2 7C56.2 7C57.2 7C58.2 7C59.2 7C60.2 7C61.2 7C62.2 7C63.2 7C64.2 7C65.2 7C66.2 7C67.2 7C68.2 7C69.2 7C70.2 7C71.2 7C72.2 7C73.2 7C74.2 7C75.2 7C76.2 7C77.2 7C78.2 7C79.2 7C83.2 7C84.2 7C85.2 7C88.2 7C89.2 7C90.2 7C91.2 7C92.2 7C93.2 7C94.2 7C95.2 7C96.2 7C97.2 7C98.2 7C99.2 7C100.2 7C101.2 7C102.2 7C105.2 7C106.2 7C107.2 7C108.2 7C109.2 7C110.2 7C111.2 7C112.2 7C113.1 7C116.2 7C117.2 7C118.2 7C119.2 7C120.2 7C121.2 7C122.2 7C123.2 7C124.2 7C125.2 7C126.2 7C127.2 7C128.2 7C129.2 7C130.2 7C131.2 7C132.2 7C133.2 7C134.2 7C135.2 7C136.2 7C137.2 7C138.2 7C139.2 7C140.2 7C141.2 7C142.2 7C143.1 7C144.1 7C145.1 7C146.1 7C147.1 7C148.1 7C149.1 7C150.1 7C152.2 7C153.2 7J1.2 7J2.2 7J3.2 7J4.8 7R18.1 7R22.2 7R23.2 7R25.2 7R26.2 7R33.1 7R42.2 7R43.2 7R49.2 7R51.2 7R54.2 7R62.2 7R71.2 7R72.2 7R73.2 7ST5.2 7ST16.2 7ST17.2 7ST18.2 7ST19.2 7U3.4(GND) 7Y1.2 7Y1.4 CT1.2 CT15.2 CT16.2 CT17.2 CT18.2 CT19.2 CT20.2 CT21.2 S7_GND1.1(TP) S7_GND2.1(TP) S7_GND3.1(TP) S7_GND4.1(TP) SITE7.4(GND_SPS_DCORE) SITE7.30(GND) SITE7.74(GND_SPS_MEM) SITE7.99(GND_SPS_AUD) SITE7.EP(EPAD) SITE7.G1 SITE7.G2 SITE7.G3 SITE7.G4 SITE7.G5 SITE7.G6 SITE7.G7 SITE7.G8 SITE7.G9 SITE7.G10 SITE7.G11 SITE7.G12 SITE7.G13 SITE7.G14 SITE7.G15 SITE7.G16 SITE7.G17 SITE7.G18 SITE7.G19 SITE7.G20 SITE7.G21 SITE7.G22 SITE7.G23 SITE7.G24 SITE7.G25 SITE7.G26 SITE7.G27 SITE7.G28 SITE7.G29 SITE7.G30 SITE7.G31 SITE7.G32 SITE7.G33 ST2.2 UT1.1(NC) UT1.2(GND) UT1.5(NC[1]) ; also on sheet 2 3 4 5 6 7 8 9 10 11 12 13 14 15 16 17 18 19 20 21 22 27 29 30 32 34 37 39
S0_GPIO5_CH: KT1.2 ; also on sheet 2
S0_LPC_060: KT1.3
S7_1_AOUT_LN: 7K10.4 7R45.1 7R67.1 7R68.1
S7_1_AOUT_LP: 7K10.5 7R69.1 7R70.1 7R75.1
S7_1_AOUT_RN: 7K14.4 7R47.1 7R63.1 7R64.1
S7_1_AOUT_RP: 7K14.5 7R65.1 7R66.1 7R74.1
S7_1_SPI_CLK: 7R15.1 7U3.6(SCLK)
S7_1_SPI_CS: 7R10.2 7U3.1(CS#)
S7_1_SPI_DATA0: 7R17.1 7U3.5(SI/SIO0)
S7_1_SPI_DATA1: 7R11.2 7U3.2(SO/SIO1)
S7_1_SPI_DATA2: 7R14.2 7R16.2 7R18.2 7U3.3(WP#/SIO2)
S7_1_SPI_DATA3: 7R12.1 7R13.1 7U3.7(RST#/SIO3)
S7_1_VDD09: 7BD1.1 7BD2.1 7BD37.1 7C60.1 7R48.2 7R76.1 7R77.1 7R78.1 7R79.1 7ST13.2
S7_1_VDD18_A: 7K26.2 7K26.5 7R50.1 S7_1V3.1(TP)
S7_1_VDD18_D: 7C113.2 7R53.2 7R81.1 7R82.1 7R83.1 7ST15.1
S7_2_AOUT_LN: 7K12.4 7R68.2
S7_2_AOUT_LP: 7K12.5 7R69.2
S7_2_AOUT_RN: 7K15.4 7R64.2
S7_2_AOUT_RP: 7K15.5 7R65.2
S7_2_VDD18_A: 7BD16.1 7BD17.1 7BD19.1 7BD20.1 7C89.1 7R50.2
S7_ATX_VD0V9: 7C65.1 7C66.1 7K21.6 7ST3.2 ; also on sheet 27
S7_ATX_VD1V8: 7J7.1 7J8.1 7J9.1 ; also on sheet 27
S7_ATX_VD33: 7BD33.1 7C131.1 7C132.1 7C133.1 7C134.1 7C135.1 7J6.2 ; also on sheet 27
S7_AVCC_DRV: 7C75.1 7C110.1 7R55.2 7ST14.1 SITE7.53(AVCC_DRV)
S7_CHIP_EN_1: 7R34.2 7SW5.1
S7_DPS_F001: 7C120.1 7C121.1 7J9.2 7K29.6 7ST11.2
S7_DPS_F002: 7C92.1 7C93.1 7C94.1 7C95.1 7J8.2 7K26.6 7ST8.2
S7_DPS_F004: 7C140.1 7C141.1 7J7.2 7K20.6 7ST12.2
S7_DPS_F006: 7C68.1 7C69.1 7C70.1 7C71.1 7C72.1 7K23.3 7K23.6 7ST4.2 S7_VD33_ALL1.1(TP)
S7_DPS_GS001: 7ST19.1
S7_DPS_GS002: 7ST18.1
S7_DPS_GS003-1: 7ST16.1
S7_DPS_GS004: 7ST17.1
S7_DPS_GS006: 7ST5.1
S7_DPS_S001: 7ST11.1
S7_DPS_S002: 7ST8.1
S7_DPS_S003-1: 7ST3.1
S7_DPS_S004: 7ST12.1
S7_DPS_S006: 7ST4.1
S7_HSDM: 7K5.8 SITE7.79(HSDM)
S7_HSDP: 7K5.2 SITE7.78(HSDP)
S7_LPC_001: 7K36.7
S7_LPC_002: 7K36.2
S7_LPC_003: 7K11.2
S7_LPC_005: 7K14.2
S7_LPC_006: 7K18.4
S7_LPC_007: 7K1.4
S7_LPC_008: 7K35.2
S7_LPC_010: 7K34.7
S7_LPC_013+: 7K5.3 7K7.2
S7_LPC_013-: 7K5.7 7K7.8
S7_LPC_016: 7K2.5
S7_LPC_017: 7K35.7
S7_LPC_019: 7K12.2
S7_LPC_021: 7K1.5
S7_LPC_022: 7K15.2
S7_LPC_023: 7K3.4
S7_LPC_024: 7J4.2 7R35.1 SITE7.69(UART2_TXD/TEST_MODE_SEL/DMIC0_CLK/GPIOF_1/PB[22])
S7_LPC_025: 7J4.1 7R34.1 SITE7.71(CHIP_EN)
S7_LPC_026: 7K2.4
S7_LPC_027: 7K10.2
S7_LPC_028: 7K10.7
S7_LPC_029: 7K13.7
S7_LPC_030: 7K16.2
S7_LPC_032: 7K15.7
S7_LPC_033: 7K14.7
S7_LPC_034: 7K18.5
S7_LPC_035: 7K12.7
S7_LPC_036: 7K34.2
S7_LPC_038: 7K13.2
S7_LPC_039: 7K3.5
S7_LPC_040: 7K11.7
S7_LPC_041: 7J4.3 7R36.1 SITE7.68(UART2_RXD/BOOT_SEL/DMIC0_DATA/GPIOF_0/PB[21])
S7_LPC_042: 7C18.2 SITE7.50(MIC_BIAS2/GPIOC_13/PA[31])
S7_LPC_044: 7J4.5 7R39.1 SITE7.58(I2S3_DOUT1/DMIC_DATA2/ICFG1/GPIOD_4/PB[11])
S7_LPC_045: 7K39.3
S7_LPC_046: SITE7.67(I2S2_DIN3/I2S3_DOUT3/SPK_CLK/SPI0_CS/GPIOE_6/PB[20])
S7_LPC_047: 7J4.7 7R41.1 SITE7.18(GPIOB_7/PA[16]/ICFG3/SPI0_CS/UART0_RTS/HP_I2C2_SCL/ANT_SEL_N)
S7_LPC_048: 7K6.4
S7_LPC_049: SITE7.8(GPIOA_5/PA[5]/TOUCH5/ADC5/UART1_TXD/SPI1_MOSI/PWM4)
S7_LPC_050: SITE7.7(GPIOA_4/PA[4]/TOUCH4/ADC4/UART1_RXD/SPI1_MISO/PWM3/HP_I2C1_SCL)
S7_LPC_051: 7C17.2 SITE7.49(MIC_BIAS1/GPIOC_12/PA[30])
S7_LPC_052: 7C21.1 SITE7.48(AVCC)
S7_LPC_053: 7J4.4 7R37.1 SITE7.57(I2S3_DOUT0/DMIC_DATA1/ICFG0/BT_LOG/GPIOD_3/PB[10])
S7_LPC_054: 7K6.5
S7_LPC_055: SITE7.10(VBAT_MEAS)
S7_LPC_057: 7K9.4
S7_LPC_058: 7J4.6 7R40.1 SITE7.17(GPIOB_6/PA[15]/ICFG2/SPI0_CLK/UART0_CTS/HP_I2C2_SDA/ANT_SEL_P)
S7_LPC_059: 7K39.6
S7_LPC_060: SITE7.66(I2S2_DIN2/I2S3_DOUT2/SPK_DATA/SPI0_CK/GPIOE_5/PB[19])
S7_LPC_A_015: 7K8.4
S7_LPC_A_020: 7K8.5
S7_LPC_B_031: 7K4.4
S7_LPC_B_037: 7K4.5
S7_LX_AUD: 7K20.3 SITE7.100(LX_AUD)
S7_LX_AUD_CH_1: 7K20.4 ; also on sheet 22
S7_LX_AUD_CH_2: 7ST14.2 ; also on sheet 22
S7_LX_DCORE: 7K21.3 SITE7.3(LX_DCORE)
S7_LX_DCORE_CH: 7K21.4 ; also on sheet 22
S7_LX_MEM: 7K29.3 SITE7.75(LX_MEM)
S7_LX_MEM_CH_1: 7K29.4 ; also on sheet 22
S7_LX_MEM_CH_2: 7ST15.2 ; also on sheet 22
S7_MIPITX_CKN: 7K36.6 SITE7.82(MIPITX_CKN)
S7_MIPITX_CKP: 7K36.3 SITE7.83(MIPITX_CKP)
S7_MIPITX_DATAN_0: 7K34.6 SITE7.85(MIPITX_DATAN_0)
S7_MIPITX_DATAN_1: 7K35.6 SITE7.80(MIPITX_DATAN_1)
S7_MIPITX_DATAP_0: 7K34.3 SITE7.86(MIPITX_DATAP_0)
S7_MIPITX_DATAP_1: 7K35.3 SITE7.81(MIPITX_DATAP_1)
S7_PA2: 7K18.3 SITE7.5(GPIOA_2/PA[2]/TOUCH2/ADC2/UART0_RXD/SPI1_CS)
S7_PA3: 7K18.6 SITE7.6(GPIOA_3/PA[3]/TOUCH3/ADC3/UART0_TXD/SPI1_CLK/LEDC/HP_I2C1_SDA)
S7_PA9_CH: 7K39.2 SITE7.12(GPIOB_0/PA[9])
S7_PA10_CH: 7K39.7 SITE7.13(GPIOB_1/PA[10])
S7_PA13: 7K6.3 SITE7.15(GPIOB_4/PA[13]/SWD_DATA/SPI0_MOSI/UART0_RXD/HP_I2C1_SDA)
S7_PA13_UART_RX: 7K6.2 7R27.1
S7_PA13_UART_RX_1: 7J2.3 7R27.2
S7_PA14: 7K6.6 SITE7.16(GPIOB_5/PA[14]/SWD_CLK/SPI0_MISO/UART0_TXD/HP_I2C1_SCL)
S7_PA14_UART_TX: 7K6.7 7R28.1
S7_PA14_UART_TX_1: 7J2.4 7R28.2
S7_PA15_1: 7R40.2 7SW5.6
S7_PA16_1: 7R41.2 7SW5.7
S7_PA20: 7K15.6 SITE7.45(MIC1_P/GPIOC_2/PA[20])
S7_PA21: 7K15.3 SITE7.46(MIC1_N/GPIOC_3/PA[21])
S7_PA22: 7K11.6 SITE7.43(MIC2_P/GPIOC_4/PA[22])
S7_PA23: 7K11.3 SITE7.44(MIC2_N/GPIOC_5/PA[23])
S7_PA24: 7K12.6 SITE7.41(MIC3_P/I2C_SDA/GPIOC_6/PA[24])
S7_PA25: 7K12.3 SITE7.42(MIC3_N/I2C_SCL/GPIOC_7/PA[25])
S7_PA28: 7K13.6 SITE7.39(MIC5_P/ANT_SEL_P/GPIOC_10/PA[28])
S7_PA29: 7K13.3 SITE7.40(MIC5_N/ANT_SEL_N/GPIOC_11/PA[29])
S7_PB3: 7K10.6 SITE7.52(AOUT_LP/GPIOC_17/PB[3])
S7_PB3_AOUT_LP_2: 7K13.5 7R70.2
S7_PB4: 7K10.3 SITE7.51(AOUT_LN/GPIOC_18/PB[4])
S7_PB4_AOUT_LN_2: 7K13.4 7R67.2
S7_PB5: 7K14.6 SITE7.54(AOUT_RP/GPIOC_19/PB[5])
S7_PB5_AOUT_RP_2: 7K11.5 7R66.2
S7_PB6: 7K14.3 SITE7.55(AOUT_RN/GPIOC_20/PB[6])
S7_PB6_AOUT_RN_2: 7K11.4 7R63.2
S7_PB10_1: 7R37.2 7SW5.4
S7_PB11_1: 7R39.2 7SW5.5
S7_PB21_1: 7R36.2 7SW5.3
S7_PB22_1: 7R35.2 7SW5.2
S7_PB23: 7C144.2 7K4.3 7R57.1 SITE7.72(UART_LOG_RXD/OTP_BYPASS/GPIOF_2/PB[23])
S7_PB23_1: 7R57.2 7SW6.1
S7_PB23_SICK: 7K4.2 7R20.1
S7_PB23_SICK_1: 7J1.3 7R20.2
S7_PB24: 7C143.2 7K4.6 7R58.1 SITE7.73(UART_LOG_TXD/UART_DOWNLOAD/GPIOF_3/PB[24])
S7_PB24_1: 7R58.2 7SW6.2
S7_PB24_SIDD: 7K4.7 7R21.1
S7_PB24_SIDD_1: 7J1.4 7R21.2
S7_PB25: 7K8.3 7R59.1 SITE7.96(SPI0_CLK/SWD_CLK/SD_D2/ICFG2/GPIOG_0/PB[25])
S7_PB25_1: 7R59.2 7SW6.3
S7_PB25_I2C_SCL: 7K8.2 7R31.1
S7_PB25_I2C_SCL_1: 7J3.3 7R31.2
S7_PB26: 7K8.6 7R60.1 SITE7.97(SPI0_CS/SWD_DATA/SD_D3/ICFG3/GPIOG_1/PB[26])
S7_PB26_1: 7R60.2 7SW6.4
S7_PB26_I2C_SDA: 7K8.7 7R32.1
S7_PB26_I2C_SDA_1: 7J3.4 7R32.2
S7_RF_A: 7C13.1 7C14.1 7C15.1 7D3.1(CATHODE_D1) 7SMP3.1
S7_RF_G: 7C6.1 7C7.1 7C8.1 7D2.1(CATHODE_D1) 7SMP2.1
S7_RFIN_A: 7C16.2 7R9.1 SITE7.29(RFIN_A/GND_(<750um))
S7_RFIN_G: 7C9.2 7R5.1 SITE7.31(RFIN_G/GND)
S7_RFIO_A: 7C11.2 7R6.1 SITE7.28(RFIO_A__(<750um))
S7_RFIO_BT: 7C1.2 7R1.1 SITE7.37(RFIO_BT)
S7_RFIO_G: 7C4.2 7R2.1 SITE7.32(RFIO_G)
S7_RREF_MEM: 7K9.3 7R43.1 SITE7.60(RREF_MEM)
S7_SPI_CLK: 7K1.7 7R15.2
S7_SPI_CLK/PB28: 7K1.6 SITE7.90(SPI_FLASH_CLK/SD_CLK/GPIOG_3/PB[28])
S7_SPI_CS: 7K3.2 7R10.1
S7_SPI_CS/PC0: 7K3.3 SITE7.95(SPI_FLASH_CS/UART1_CTS/SD_CD/GPIOG_7/PC[0])
S7_SPI_D0/PB29: 7K1.3 SITE7.91(SPI_FLASH_DATA0/UART1_RXD/SD_D0/GPIOG_4/PB[29])
S7_SPI_D1/PB31: 7K3.6 SITE7.94(SPI_FLASH_DATA1/UART1_RTS/SD_WP/GPIOG_6/PB[31])
S7_SPI_D2/PB30: 7K2.6 SITE7.92(SPI_FLASH_DATA2/UART1_TXD/SD_D1/GPIOG_5/PB[30])
S7_SPI_D3/PB27: 7K2.3 SITE7.89(SPI_FLASH_DATA3/SD_CMD/GPIOG_2/PB[27])
S7_SPI_DATA0: 7K1.2 7R17.2
S7_SPI_DATA1: 7K3.7 7R11.1
S7_SPI_DATA2: 7K2.7 7R16.1
S7_SPI_DATA3: 7K2.2 7R13.2
S7_U1_VC1: 7K39.5 7U1.4(VCTL)
S7_U2_VC1: 7K39.4 7U2.4(VCTL)
S7_VA09_MIPI: 7BD37.2 7C152.1 SITE7.84(VA09_MIPI/VA09_CK/VA09_DA)
S7_VA09_PLL: 7BD1.2 7C44.1 SITE7.11(VA09_PLL/VD09_CORE0)
S7_VA09_USB: 7BD2.2 7C45.1 SITE7.77(VA09_USB)
S7_VA13_AFE: 7BD20.2 7C88.1 SITE7.19(VA13_AFE)
S7_VA13_SYN: 7BD16.2 7C78.1 SITE7.23(VR13_SYN)
S7_VA33_SYN: 7BD13.2 7C64.1 SITE7.24(VR33_SYN)
S7_VA33_XTAL: 7BD5.2 7C48.1 SITE7.20(VA33_XTAL)
S7_VD09_CORE1: 7C47.1 7R76.2 SITE7.56(VD09_CORE1/VD09MEM0)
S7_VD09_CORE2: 7C49.1 7R77.2 SITE7.64(VD09_CORE2/VD09_MEM1)
S7_VD09_CORE3: 7C54.1 7R78.2 SITE7.87(VD09_CORE3/VA09_PLL)
S7_VD09_CORE4: 7C58.1 7R79.2 SITE7.98(VD09_CORE4)
S7_VD13_FE: 7BD19.2 7C85.1 SITE7.36(VD13_FE)
S7_VD13_RF: 7BD17.2 7C79.1 SITE7.25(VD13_RF)
S7_VD33_ALL: 7BD3.1 7BD5.1 7BD7.1 7BD9.1 7BD11.1 7BD12.1 7BD13.1 7BD15.1 7BD18.1 7BD21.1 7BD22.1 7BD23.1 7BD28.1 7BD29.1 7BD30.1 7BD31.1 7BD32.1 7BD36.1 7C67.1 7C96.1 7C101.1 7C122.1 7C129.1 7J5.1 7J6.1 7K23.2 7K23.7
S7_VD33_CM_BT: 7BD21.2 7C90.1 7C91.1 SITE7.35(VD33_CM_BT)
S7_VD33_EX_FLASH: 7BD32.2 7C22.1 7C127.1 7C128.1 7R12.2 7R14.1 7U3.8(VCC)
S7_VD33_IO0: 7BD7.2 7C52.1 SITE7.9(VA33_PLL/VD33_IO0)
S7_VD33_IO2: 7BD9.2 7C56.1 SITE7.59(VD33_IO2/VD33_MEM)
S7_VD33_IO3: 7BD11.2 7C59.1 SITE7.70(VD33_IO3/VDD_IO4/VA33_USB)
S7_VD33_IO6: 7BD12.2 7C61.1 SITE7.88(VD33_IO6/VDD33_IO5/VD33_FLASH)
S7_VD33_SPS_AUD: 7BD30.2 7C123.1 7C124.1 SITE7.1(VD33_SPS_AUD)
S7_VD33_SPS_DCORE: 7BD28.2 7C111.1 7C112.1 SITE7.2(VD33_SPS_DCORE)
S7_VD33_SPS_MEM: 7BD31.2 7C125.1 7C126.1 SITE7.76(VD33_SPS_MEM)
S7_VD33PA_A: 7BD23.2 7C99.1 7C100.1 SITE7.27(VD33PA_A)
S7_VD33PA_BT: 7BD18.2 7C83.1 7C84.1 SITE7.38(VD33PA_BT)
S7_VD33PA_G: 7BD15.2 7C76.1 7C77.1 SITE7.33(VD33PA_G)
S7_VD33PAD_A: 7BD22.2 7C97.1 7C98.1 SITE7.26(VD33PAD_A)
S7_VD33PAD_G: 7BD36.2 7C73.1 7C74.1 SITE7.34(VD33PAD_G)
S7_VD1833_IO1: 7BD3.2 7C46.1 SITE7.14(VD1833_IO1)
S7_VD1833_SDIO: 7BD29.2 7C118.1 7C119.1 SITE7.93(VD1833_SDIO)
S7_VD_MEM0: 7C102.1 7R81.2 SITE7.61(VD_MEM0)
S7_VD_MEM1: 7C105.1 7R82.2 SITE7.62(VD_MEM1)
S7_VD_MEM2: 7C107.1 7R83.2 SITE7.65(VD_MEM2)
S7_VDD09: 7K22.2 7K22.5 7K31.4 7R48.1 S7_VDD09.1(TP)
S7_VDD09_CH: 7ST13.1 ; also on sheet 22
S7_VDD18_A: 7K25.2 7K25.5 7K26.3 7K32.4 7R55.1 S7_VDD18_A.1(TP)
S7_VDD18_D: 7K28.2 7K28.5 7K30.4 7R29.2 7R53.1 S7_VDD18_D.1(TP)
S7_VDD33: 7BD33.2 7C130.1 7R19.1 7R24.1 7R30.1 7R38.2 7R61.2 7U1.6(VDD) 7U2.6(VDD)
S7_VDD33_J1: 7J1.1 7R19.2
S7_VDD33_J2: 7J2.1 7R24.2
S7_VDD33_J3: 7J3.1 7R30.2
S7_VREF_DRAM: 7C153.1 7K16.3 SITE7.63(VREF_DRAM/NC(PSRAM))
S7_XI: 7C25.2 7Y1.1 SITE7.22(XI)
S7_XO: 7C23.2 7Y1.3 SITE7.21(XO)
S4567_CBIT_001: 7K7.9(V-) ; also on sheet 14 17 20
S4567_CBIT_003: 7K6.8(V-) ; also on sheet 14 17 20
S4567_CBIT_004: 7K2.8(V-) ; also on sheet 14 17 20
S4567_CBIT_005: 7K3.8(V-) ; also on sheet 14 17 20
S4567_CBIT_006: 7K35.8(V-) ; also on sheet 14 15 18 21
S4567_CBIT_008: 7K30.8(V-) ; also on sheet 14 16 19 22
S4567_CBIT_009: 7K32.8(V-) ; also on sheet 14 16 19 22
S4567_CBIT_010: 7K31.8(V-) ; also on sheet 14 16 19 22
S4567_CBIT_011: 7K29.8(V-) ; also on sheet 14 16 19 22
S4567_CBIT_012: 7K28.8(V-) ; also on sheet 14 16 19 22
S4567_CBIT_013: 7K8.8(V-) ; also on sheet 14 17 20
S4567_CBIT_014: 7K26.8(V-) ; also on sheet 14 16 19 22
S4567_CBIT_015: 7K34.8(V-) ; also on sheet 14 15 18 21
S4567_CBIT_016: 7K16.8(V-) ; also on sheet 14 17 20
S4567_CBIT_017: 7K21.8(V-) ; also on sheet 14 16 19 22
S4567_CBIT_018: 7K18.8(V-) ; also on sheet 14 15 18 21
S4567_CBIT_019: 7K22.8(V-) ; also on sheet 14 16 19 22
S4567_CBIT_020: 7K9.8(V-) ; also on sheet 14 17 20
S4567_CBIT_022: 7K19.8(V-) ; also on sheet 14 15 18 21
S4567_CBIT_023: 7K23.8(V-) ; also on sheet 14 16 19 22
S4567_CBIT_024: 7K20.8(V-) ; also on sheet 14 16 19 22
S4567_CBIT_025: 7K13.8(V-) ; also on sheet 14 15 18 21
S4567_CBIT_026: 7K14.8(V-) ; also on sheet 14 15 18 21
S4567_CBIT_027: 7K15.8(V-) ; also on sheet 14 15 18 21
S4567_CBIT_028: 7K25.8(V-) ; also on sheet 14 16 19 22
S4567_CBIT_029: 7K10.8(V-) ; also on sheet 14 15 18 21
S4567_CBIT_030: 7K11.8(V-) ; also on sheet 14 15 18 21
S4567_CBIT_031: 7K12.8(V-) ; also on sheet 14 15 18 21
S4567_CBIT_032: 7K39.8(V-) ; also on sheet 14 17 20
S4567_CBIT_033: 7K1.8(V-) ; also on sheet 14 17 20
S4567_CBIT_035: 7K5.9(V-) ; also on sheet 14 17 20
S4567_CBIT_036: 7K36.8(V-) ; also on sheet 14 15 18 21
S4567_CBIT_037: 7K4.8(V-) ; also on sheet 14 17 20
SA_CBIT_021: KT1.8(V-) ; also on sheet 2
SA_DPS_F005: CT16.1 CT17.1 CT18.1 CT19.1 CT20.1 CT21.1 ST1.2 Temp_measurement.1(TP) UT1.4(VDD)
SA_DPS_GS005: ST2.1
SA_DPS_S005: ST1.1
SA_IO_TMP235ADC_2: CT1.1 CT15.1 KT1.4 RT1.1
VP12: 7K1.1(V+) 7K2.1(V+) 7K3.1(V+) 7K4.1(V+) 7K5.1(V+) 7K6.1(V+) 7K7.1(V+) 7K8.1(V+) 7K9.1(V+) 7K10.1(V+) 7K11.1(V+) 7K12.1(V+) 7K13.1(V+) 7K14.1(V+) 7K15.1(V+) 7K16.1(V+) 7K18.1(V+) 7K19.1(V+) 7K20.1(V+) 7K21.1(V+) 7K22.1(V+) 7K23.1(V+) 7K25.1(V+) 7K26.1(V+) 7K28.1(V+) 7K29.1(V+) 7K30.1(V+) 7K31.1(V+) 7K32.1(V+) 7K34.1(V+) 7K35.1(V+) 7K36.1(V+) 7K39.1(V+) KT1.1(V+) ; also on sheet 2 3 4 5 6 7 8 9 10 11 12 13 14 15 16 17 18 19 20 21 22 27 29 38
N26344713: RT1.2 UT1.3(VO)
N27493233: 7C10.1 7R5.2 7U1.3(RF2)
N27493239: 7C7.2 7U1.5(ANT)
N27493242: 7R4.1 7U1.1(RF1)
N27493293: 7C6.2 7R3.2
N27493302: 7C19.1 7R9.2 7U2.1(RF1)
N27493309: 7C14.2 7U2.5(ANT)
N27493316: 7C12.1 7R6.2 7R7.1 7R8.2
N27493318: 7C13.2 7R7.2
N27493337: 7BD27.2 7C24.1 7K16.4
N27493347: 7K5.6 7R22.1
N27493349: 7K5.4 7R25.1
N27493352: 7R8.1 7U2.3(RF2)
N27493358: 7C5.1 7R2.2 7R3.1 7R4.2
N27493386: 7C2.1 7C3.1 7R1.2
N27493391: 7C2.2 7D1.1(CATHODE_D1) 7SMP1.1
N27493509: 7K7.6 7R23.1
N27493510: 7K7.4 7R26.1
N27493515: 7BD27.1 7R29.1 7R33.2
N27493642: 7C20.1 SITE7.47(VREF_AUDIO)
N27497241: 7K18.2 7K19.3
N27497242: 7K18.7 7K19.6
N27497245: 7C39.1 7K19.4
N27497246: 7C38.2 7K19.2
N27497249: 7C41.1 7K19.5
N27497250: 7C40.2 7K19.7
N27497281: 7R47.2 7R74.2
N27497363: 7R45.2 7R75.2
N27497379: 7C145.2 7K34.4
N27497380: 7C146.2 7K34.5
N27497387: 7C147.2 7K35.4
N27497388: 7C148.2 7K35.5
N27497391: 7C149.2 7K36.4
N27497392: 7C150.2 7K36.5
N27498479: 7K21.2 7L1.1
N27498509: 7K29.2 7L3.1
N27498510: 7C106.1 7C108.1 7C109.1 7K28.3 7L3.2
N27498521: 7K28.4 7R54.1
N27498525: 7C116.1 7C117.1 7K28.6 7K29.5
N27498548: 7C53.1 7C55.1 7C57.1 7K22.3 7L1.2
N27498560: 7K22.4 7R49.1
N27498564: 7C62.1 7C63.1 7K21.5 7K22.6
N27498679: 7K20.2 7L4.1
N27498680: 7C136.1 7C137.1 7C138.1 7K25.3 7L4.2
N27498691: 7K25.4 7R51.1
N27498693: 7C139.1 7C142.1 7K20.5 7K25.6
N27498799: 7K30.3 7R71.1
N27498801: 7K31.3 7R72.1
N27498803: 7K32.3 7R73.1
N27691430: 7R61.1 7SW6.6
N27691434: 7R62.1 7SW6.5
N27691556: 7R38.1 7SW5.10
N27691560: 7R42.1 7SW5.9

Not connected (* = marked no-connect by the designer): 7K7 3* 7*; 7K9 2* 5* 6* 7*; 7K16 5* 6* 7*; 7K20 7*; 7K21 7*; 7K22 7*; 7K23 4* 5*; 7K25 7*; 7K26 4* 7*; 7K28 7*; 7K29 7*; 7K30 2* 5* 6* 7*; 7K31 2* 5* 6* 7*; 7K32 2* 5* 6* 7*; 7SW5 8*; KT1 5* 6* 7*; SITE7 GH1* GH2* GH3* GH4* NUT1* NUT2* NUT3* NUT4*

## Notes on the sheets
sheet 23
- WIFI/BT_RF
- place by Z-shape
- R3 and R4 Share PAD,
  Default R3
- C6 and C7 Share PAD,
  Default C6
- place by Z-shape
- place by Z-shape
- R7 and R8 Share PAD,
  Default R7
- C13 and C14 Share PAD,
  Default C13
- place by Z-shape
- place by Z-shape
- GND Shielding
- FLASH
- RF SW Channel  and PA9.10 share one Channel
- GND Shielding
- GND Shielding
- Debug
- Mark On Board
- 1.S0_VDD33
- 2.GND
- 3.S0_SICK
- DSSC
- 4.S0_SIDD
- USB
- GND Shielding
- SIC
- Debug
- Mark On Board
- 1.S0_VDD33
- 2.GND
- 3.S0_UART_RX
- DIFF 90ohm
- 4.S0_UART_TX
- DIFF 90ohm
- UART
- XTAL
- VREF_DRAM
- Mark On Board
- GND Shielding
- Debug
- Close To DUT
- 1.S0_VDD33
- 2.GND
- 3.S0_I2C_SCL
- DSSC
- 4.S0_I2C_SDA
- BT_I2C
- Mark On Board
- GND Shielding
- 1.S0_CHIP_EN
- 2.S0_PB22_TEST_MODE_SEL
- 3.S0_PB21_BOOT_SEL_FLASH
- 4.S0_PB10/ICFG0
- 5.S0_PB11/ICFG1
- 6.S0_PA15/ICFG2
- RREF
- 7.S0_PA16/ICFG3
- 8.NC
- Close To DUT
- Close to Relay
sheet 24
- AUDIO ADC Test
- MIPI Test
- GND Shielding
- GND Shielding
- CAP TOUCH Test
- GND Shielding
sheet 25
- CLOSE TO DUT
- POWER_VD09
- POWER_VD1833
- CLOSE TO DUT
- 110mA
- 5mA
- 33mA
- C48 TOP
- 20mA
- 102mA
- 35mA
- 105mA
- 35mA
- 112mA
- 25mA
- 50mA
- Mark On Board : S0_VDD09
- C58 TOP
- 30mA
- 50mA
- 10mA
- C64 TOP
- 200mA
- CLOSE TO DUT
- 200mA
- POWER_VD18_AUD
- CLOSE TO DUT
- Mark On Board : S0_VDD18_A
- 200mA
- 100mA
- C75 TOP
- 50mA
- Mark On Board : S0_VDD33
- CLOSE TO DUT
- CLOSE TO DUT
- 45mA
- 60mA
- C78 TOP
- 80mA
- C79 TOP
- 45mA
- C97,C98 TOP
- 300mA
- 25mA
- C88 TOP
- C99,C100 TOP
- POWER_VD18_DDR
- CLOSE TO DUT
- CLOSE TO DUT
- 155mA
- 62mA
- C111,C112 TOP
- 62mA
- 30mA
- 62mA
- Mark On Board : S0_VDD18_D
- C107 TOP
- 107mA
- C123,C124 TOP
- 160mA
- C125,C126 TOP
- 50mA
- Calibration Loading SCH
sheet 26
- for temp measurement
- for temp measurement (board edge)
- 15A
